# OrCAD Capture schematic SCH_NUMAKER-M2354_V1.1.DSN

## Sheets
1 Page08_LCD: size A; title: LCD interface; rev: V1.1; note: NuMaker-M2354
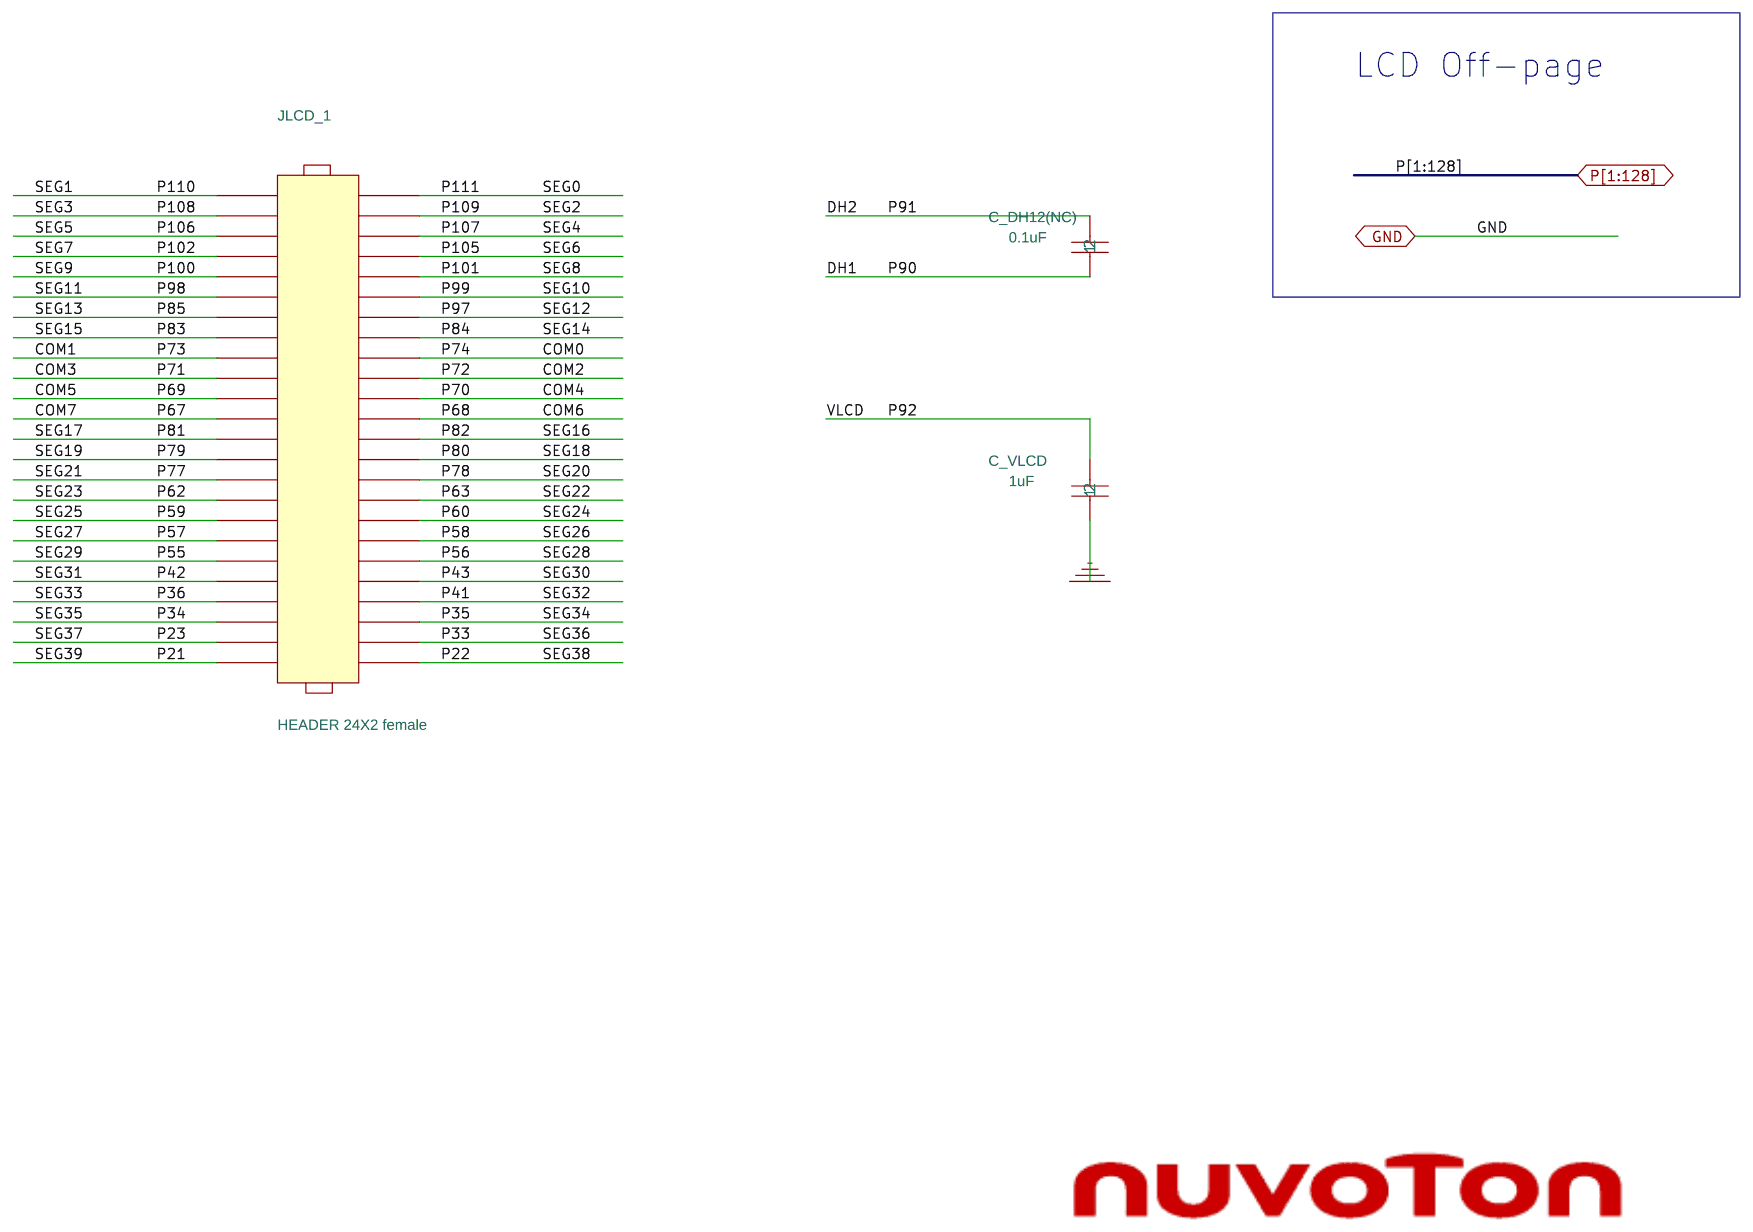
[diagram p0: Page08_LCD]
2 Page00-Nu-Link2-Me: size A3; title: Nu-Link2-Me; rev: 1.0; company: CACHEN; note: Nu-Link2-Me
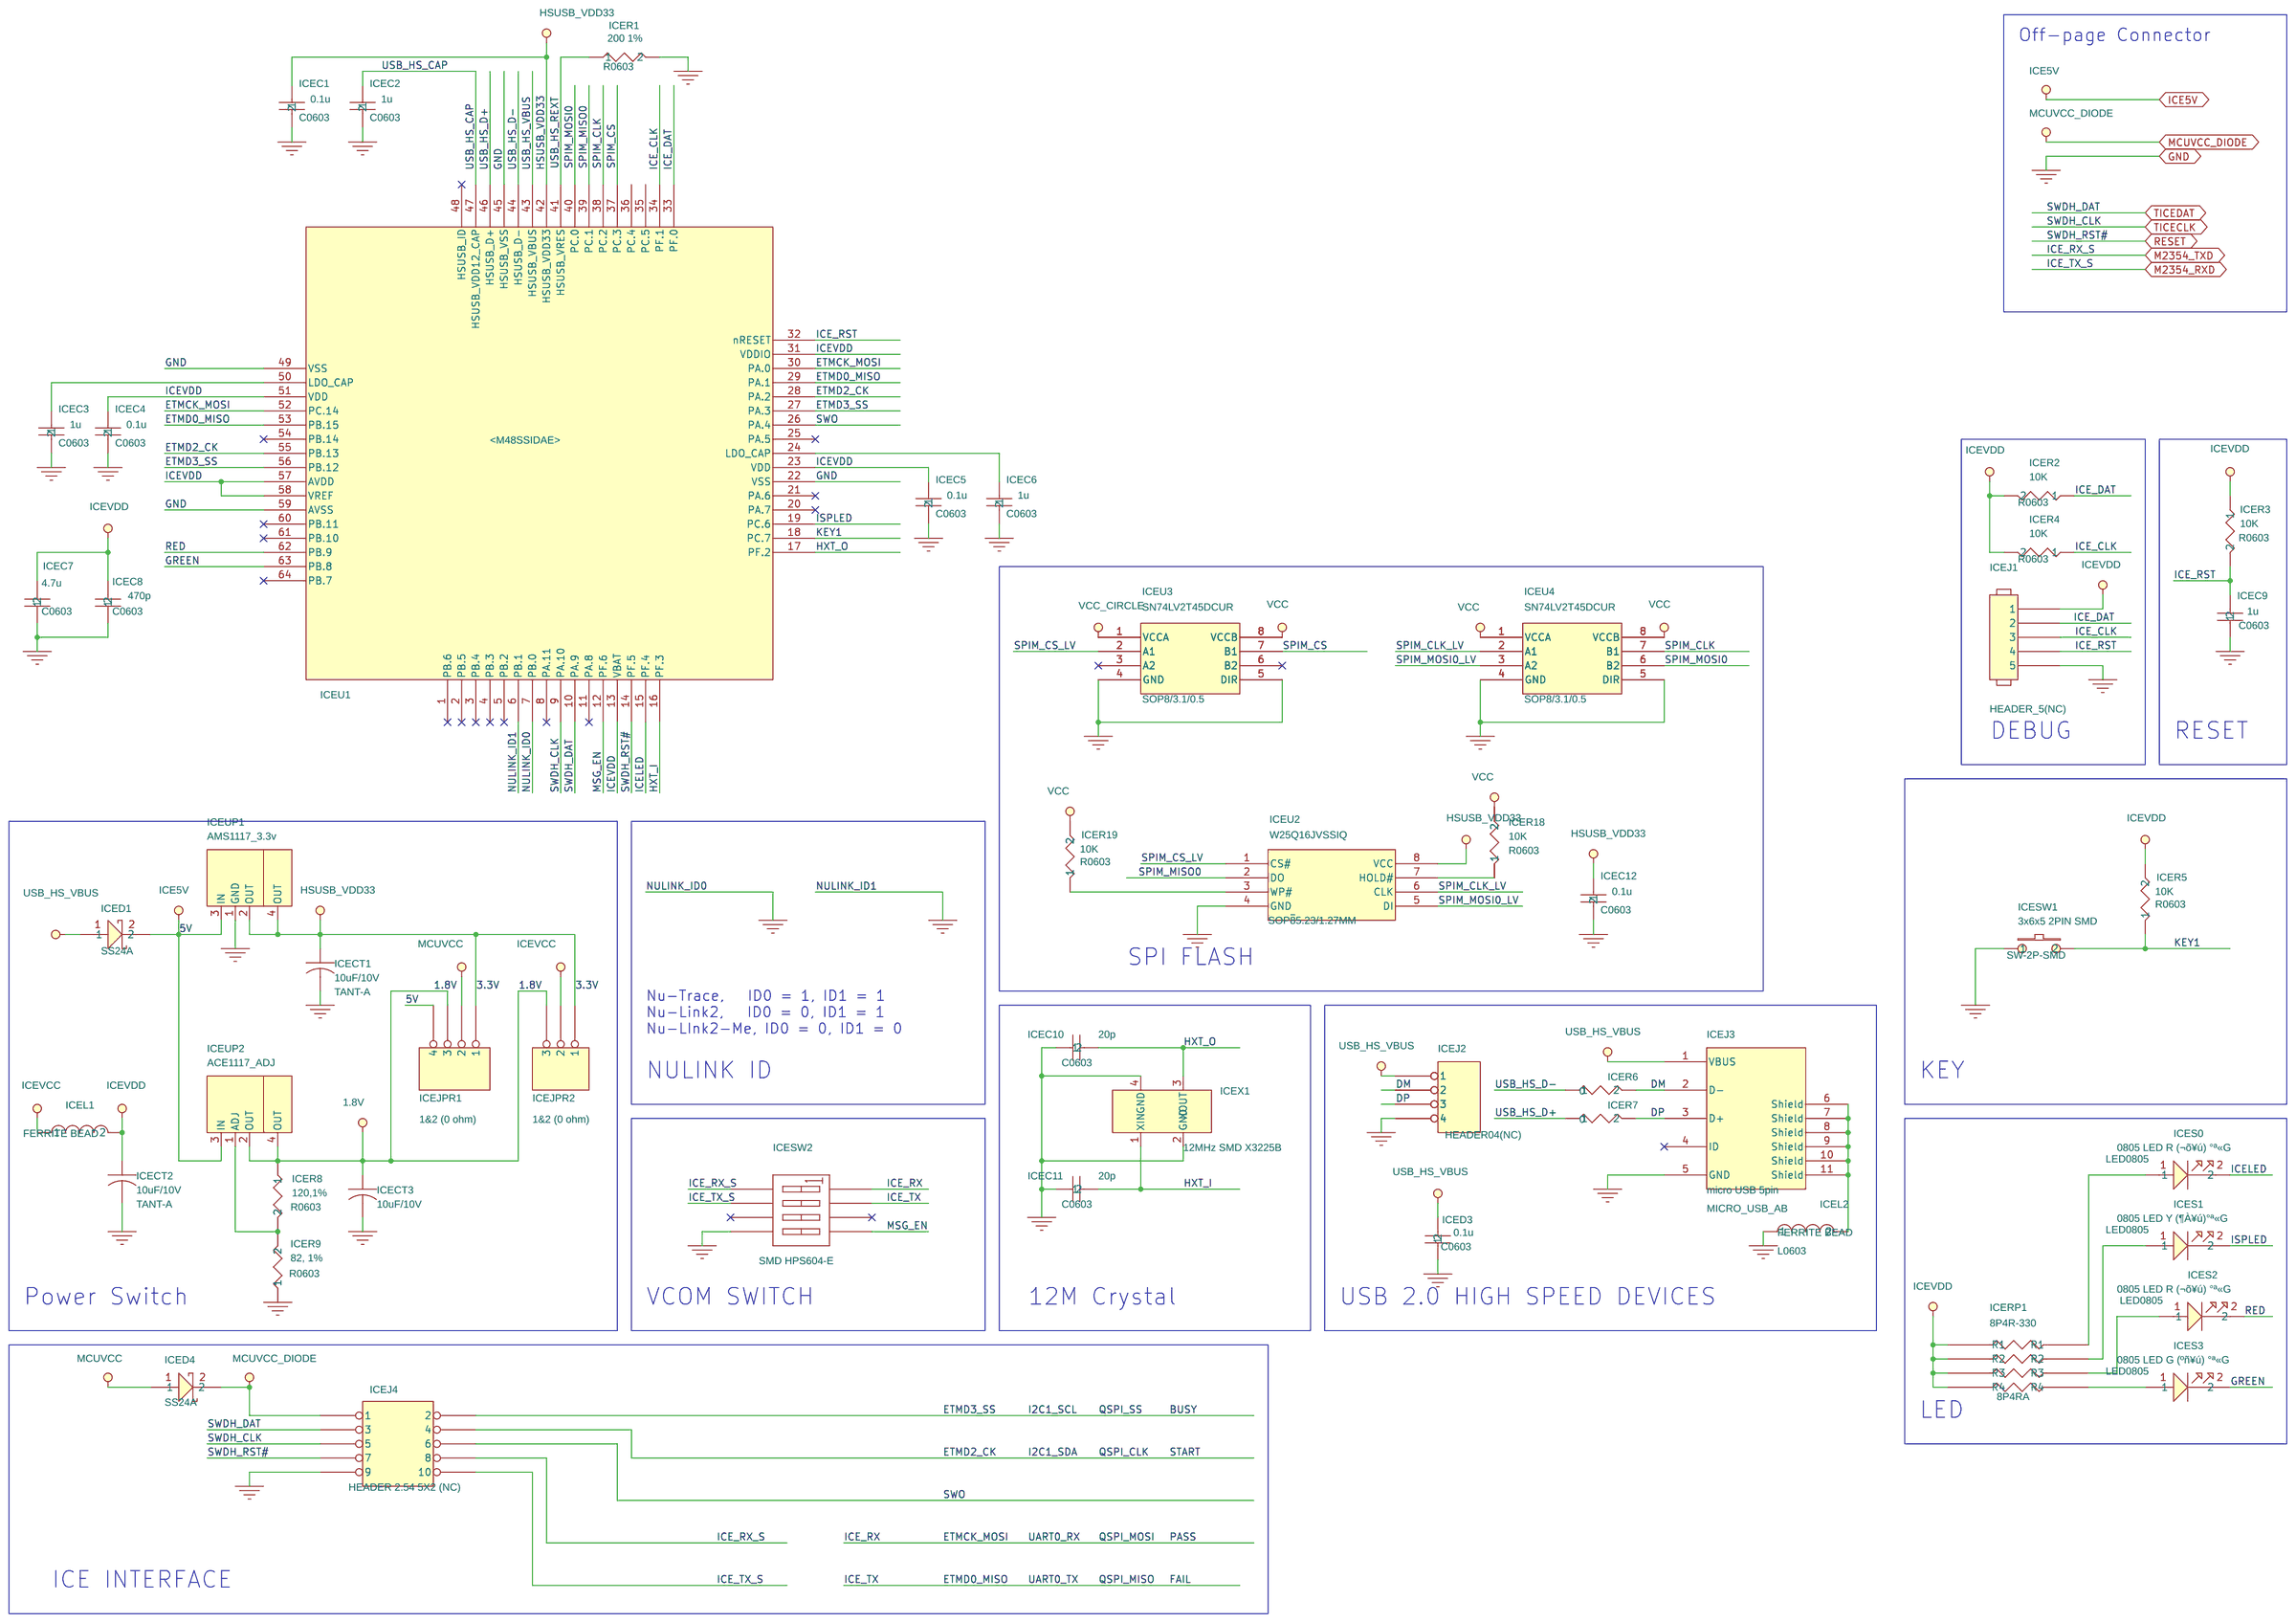
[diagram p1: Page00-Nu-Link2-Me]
3 Page07_WIFI Module: size A4; title: WIFI Module(ESP-12)
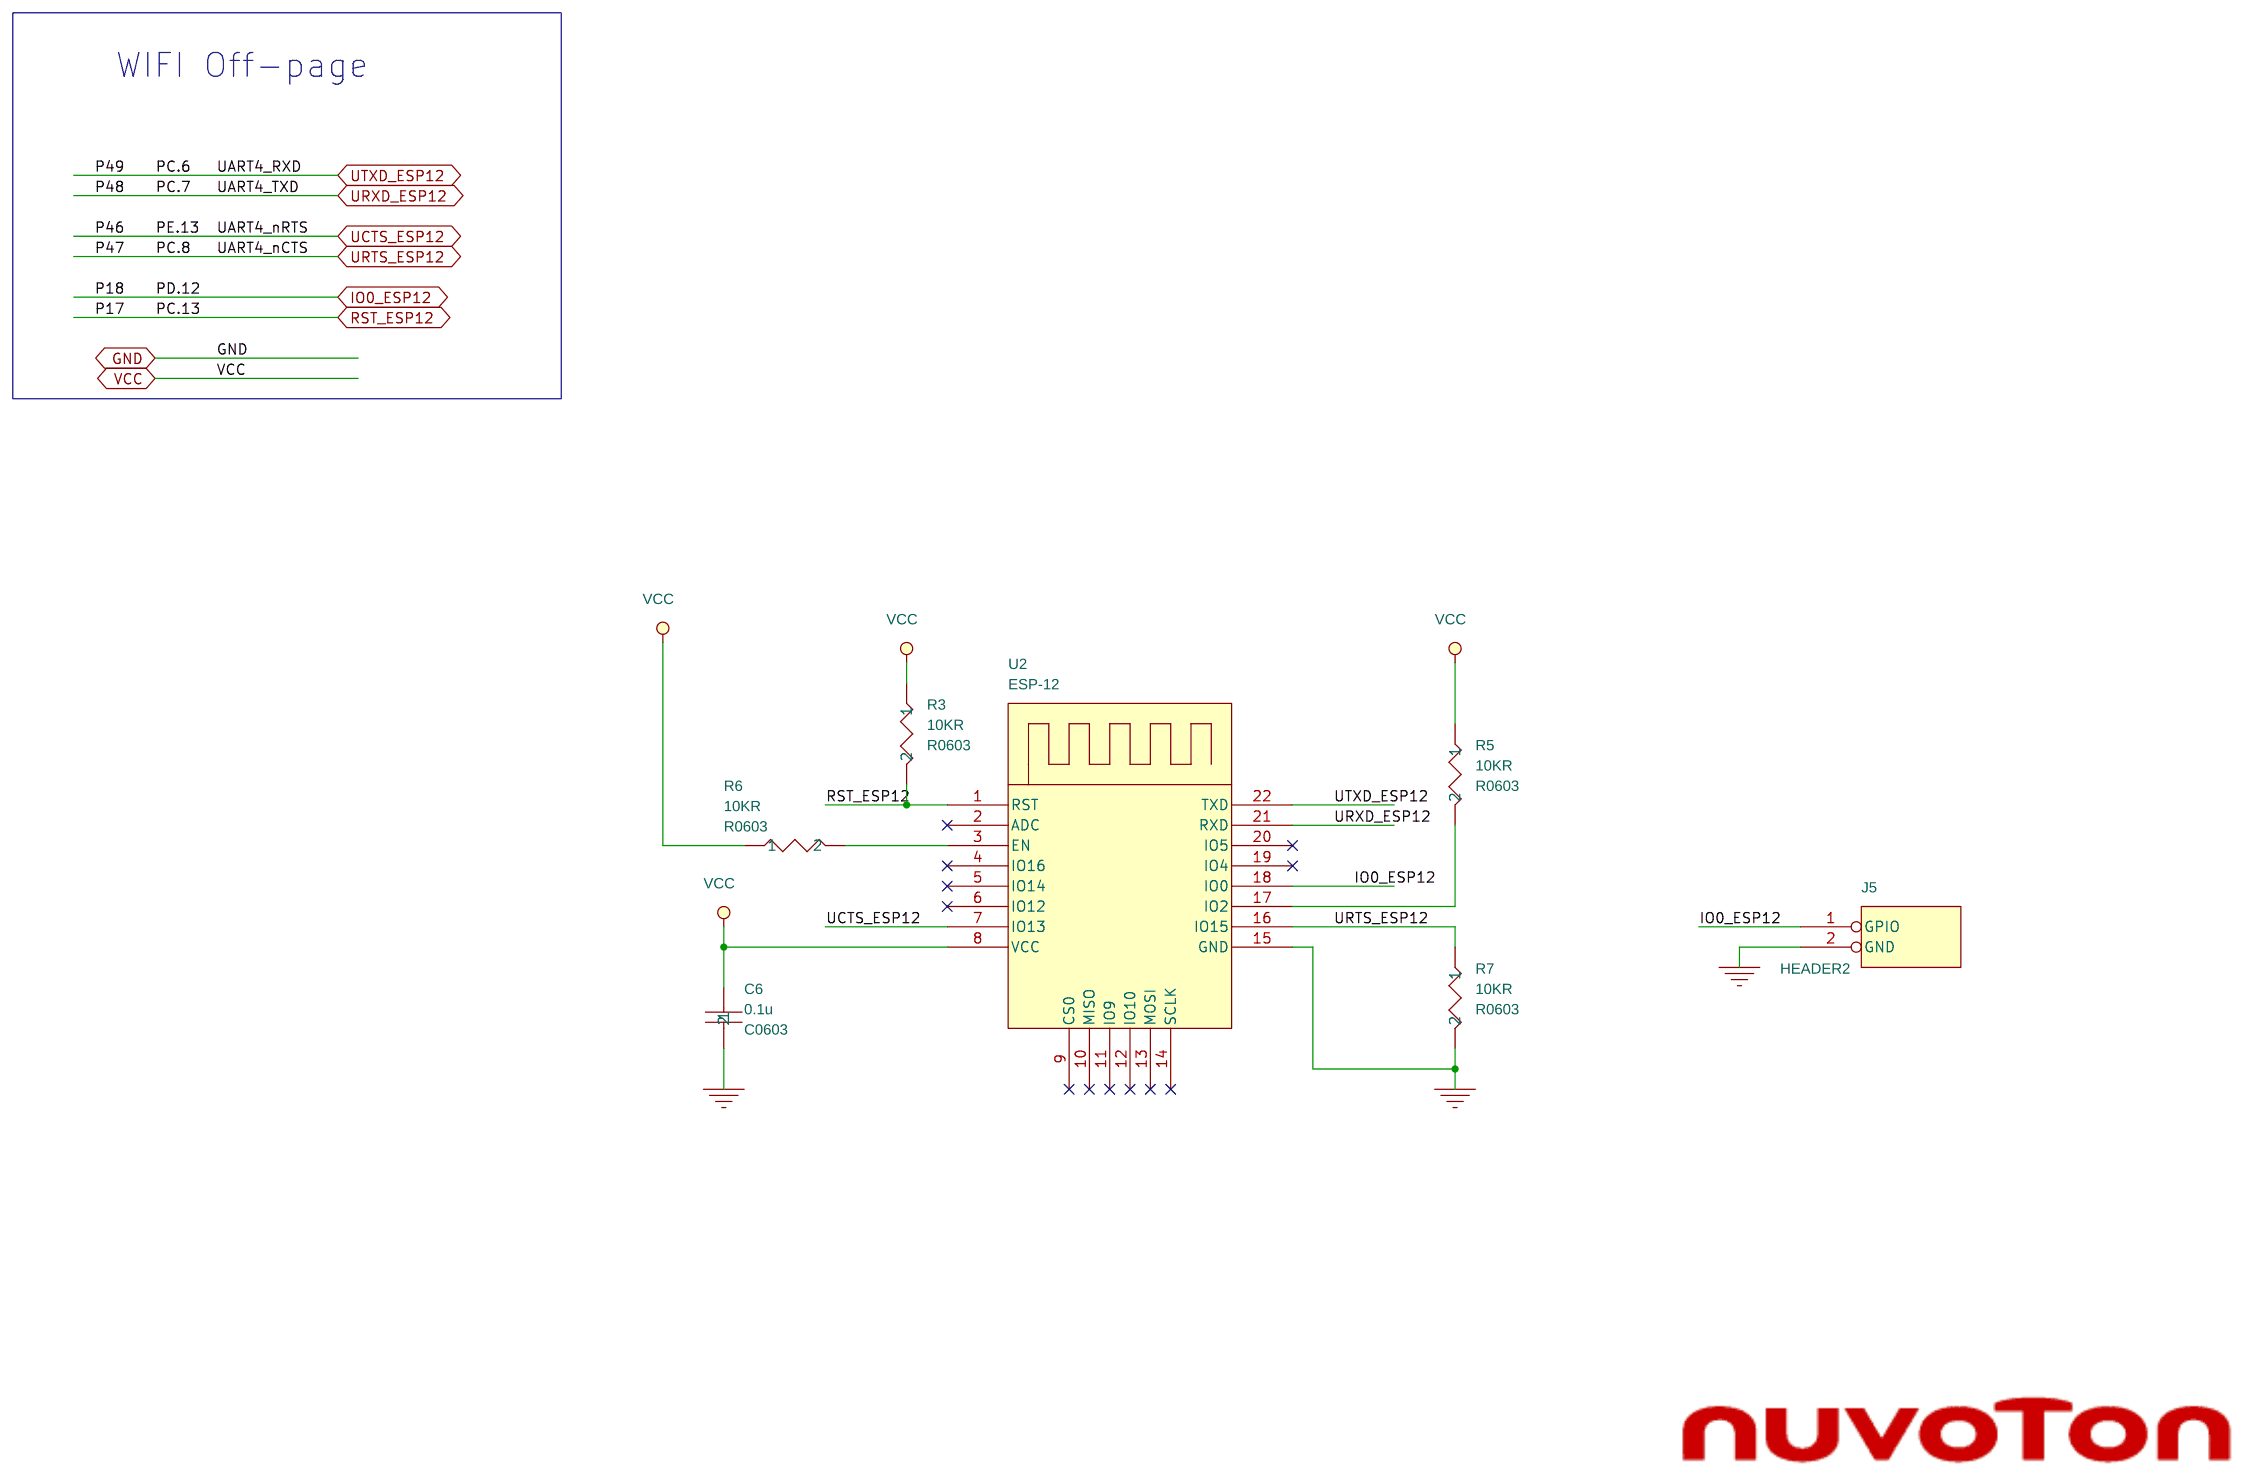
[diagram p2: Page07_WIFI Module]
4 Page01_M2354 MCU: size Custom; title: M2354KJFAE(LQFP128) MCU
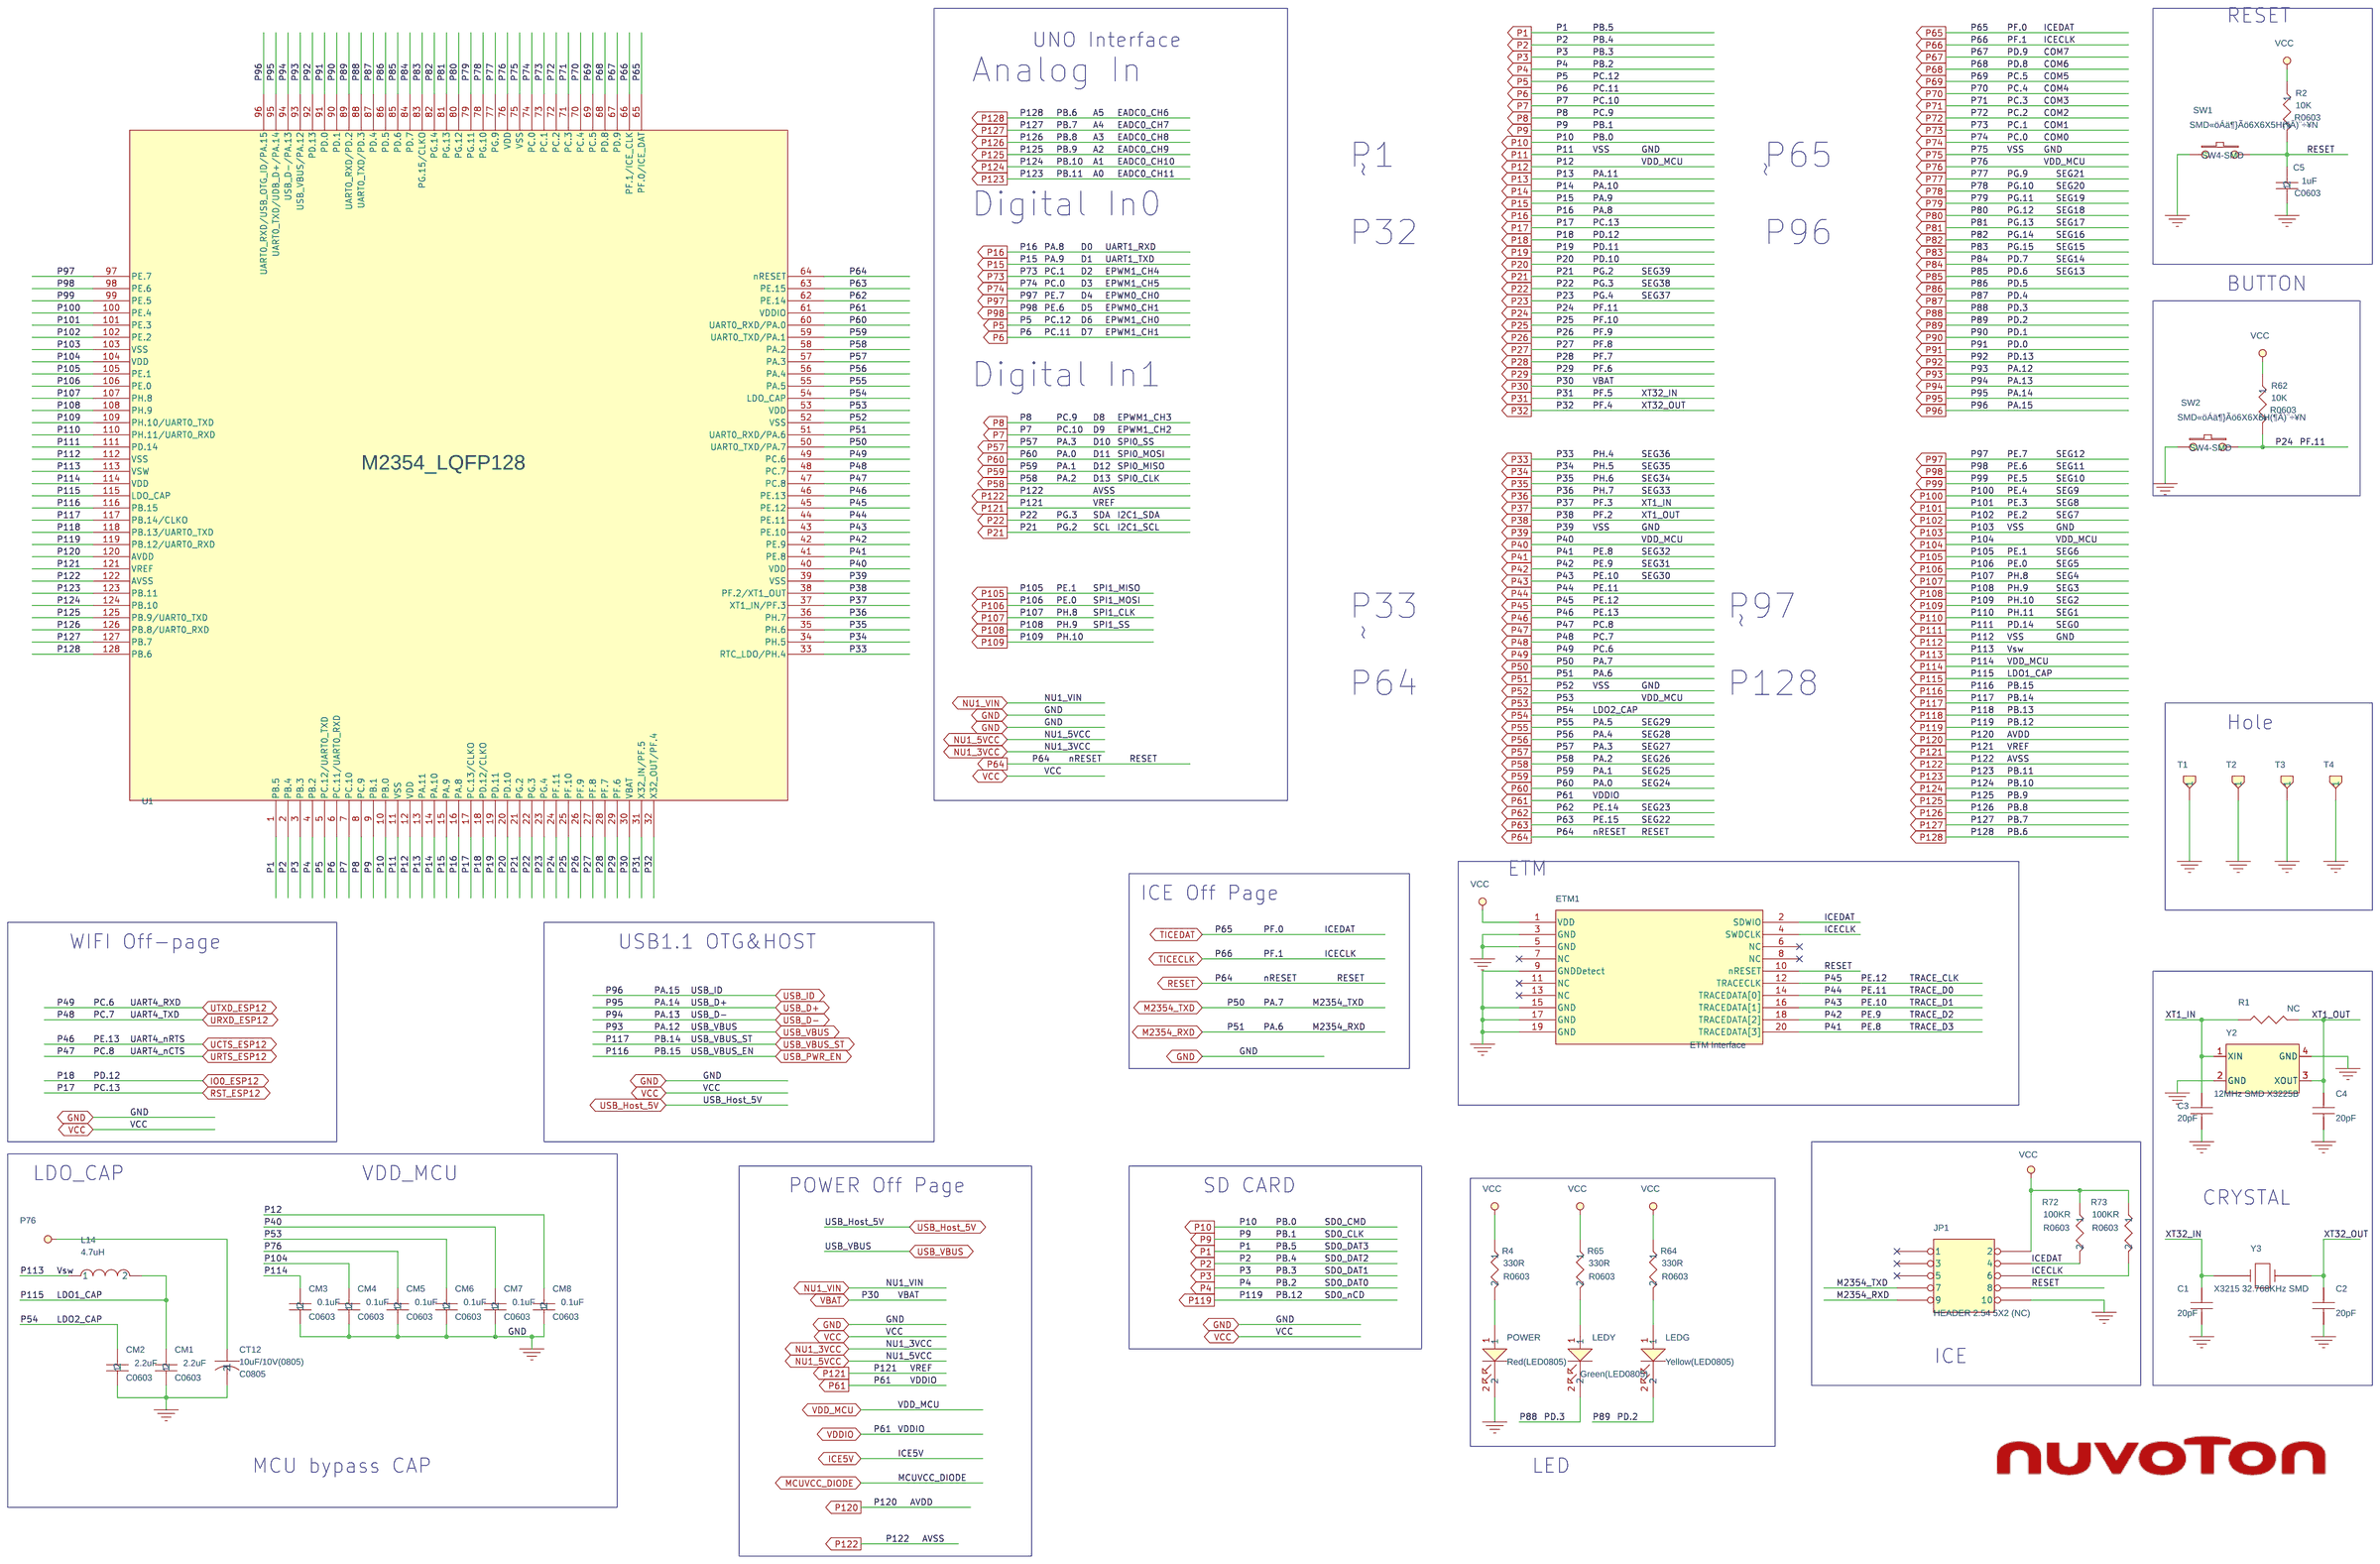
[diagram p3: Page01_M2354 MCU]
5 Page02_USB OTG Host Device: size A4; title: USB OTG
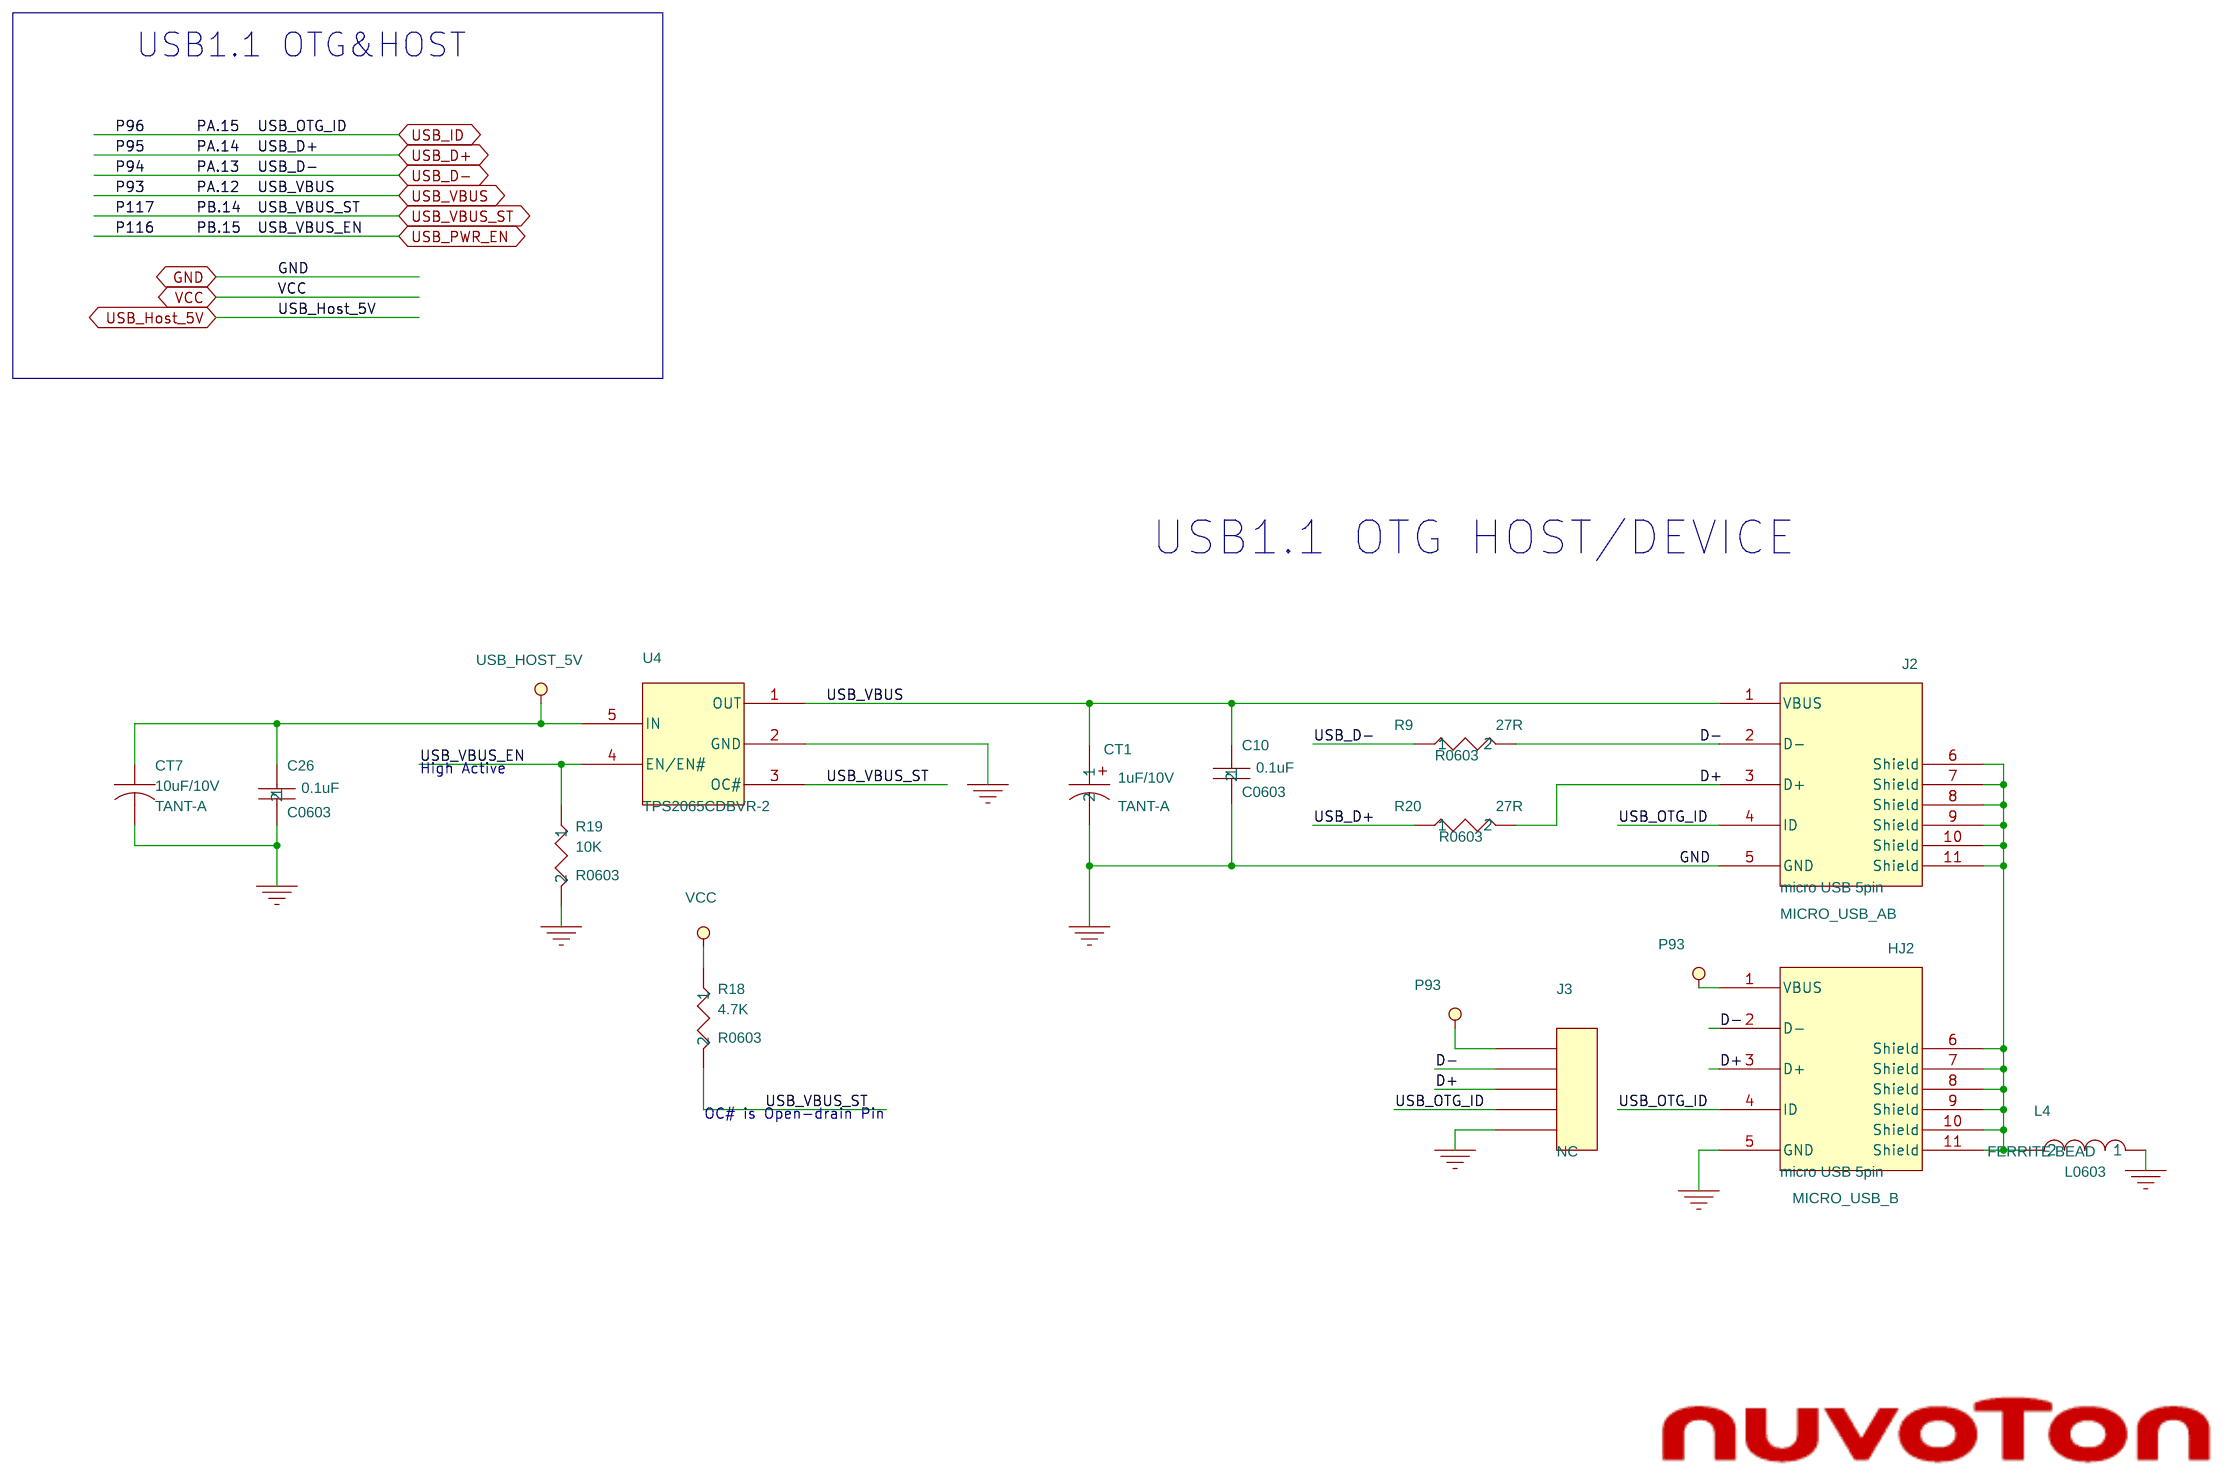
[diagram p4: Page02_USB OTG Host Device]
6 Page03_Power: size Custom; title: POWER
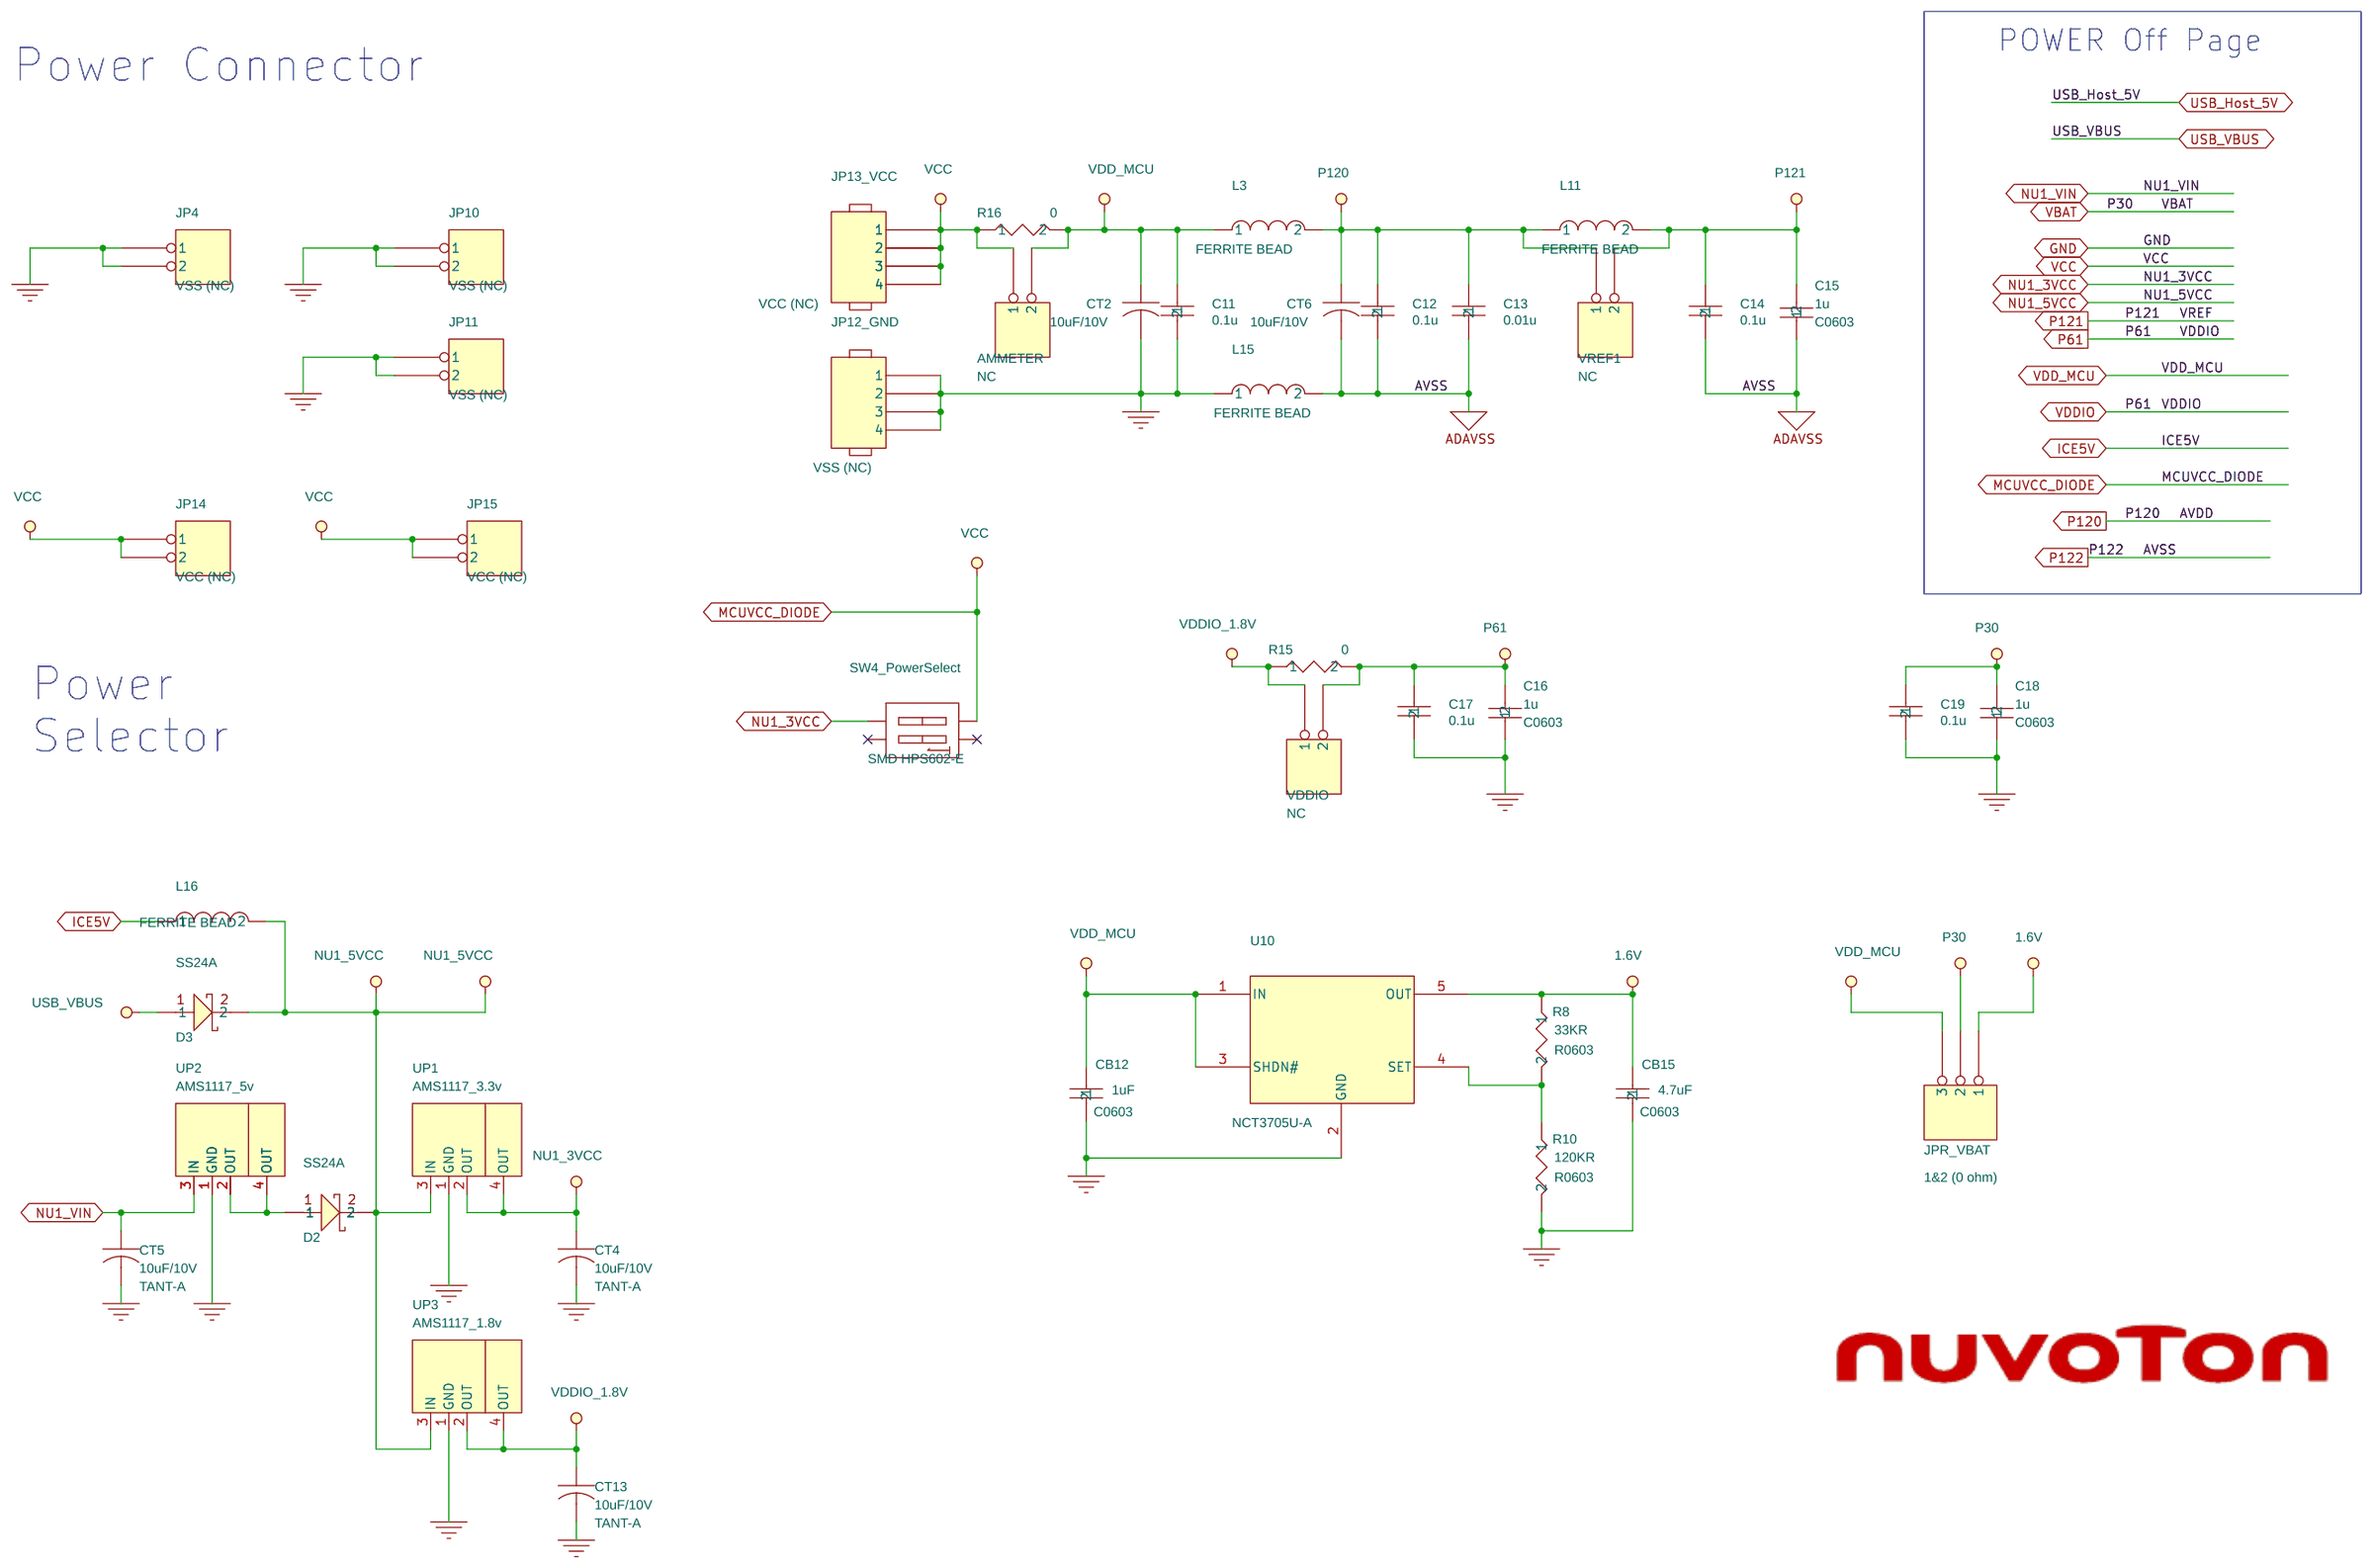
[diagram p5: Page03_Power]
7 Page04_MCU Connector: size A4; title: MCU Connector
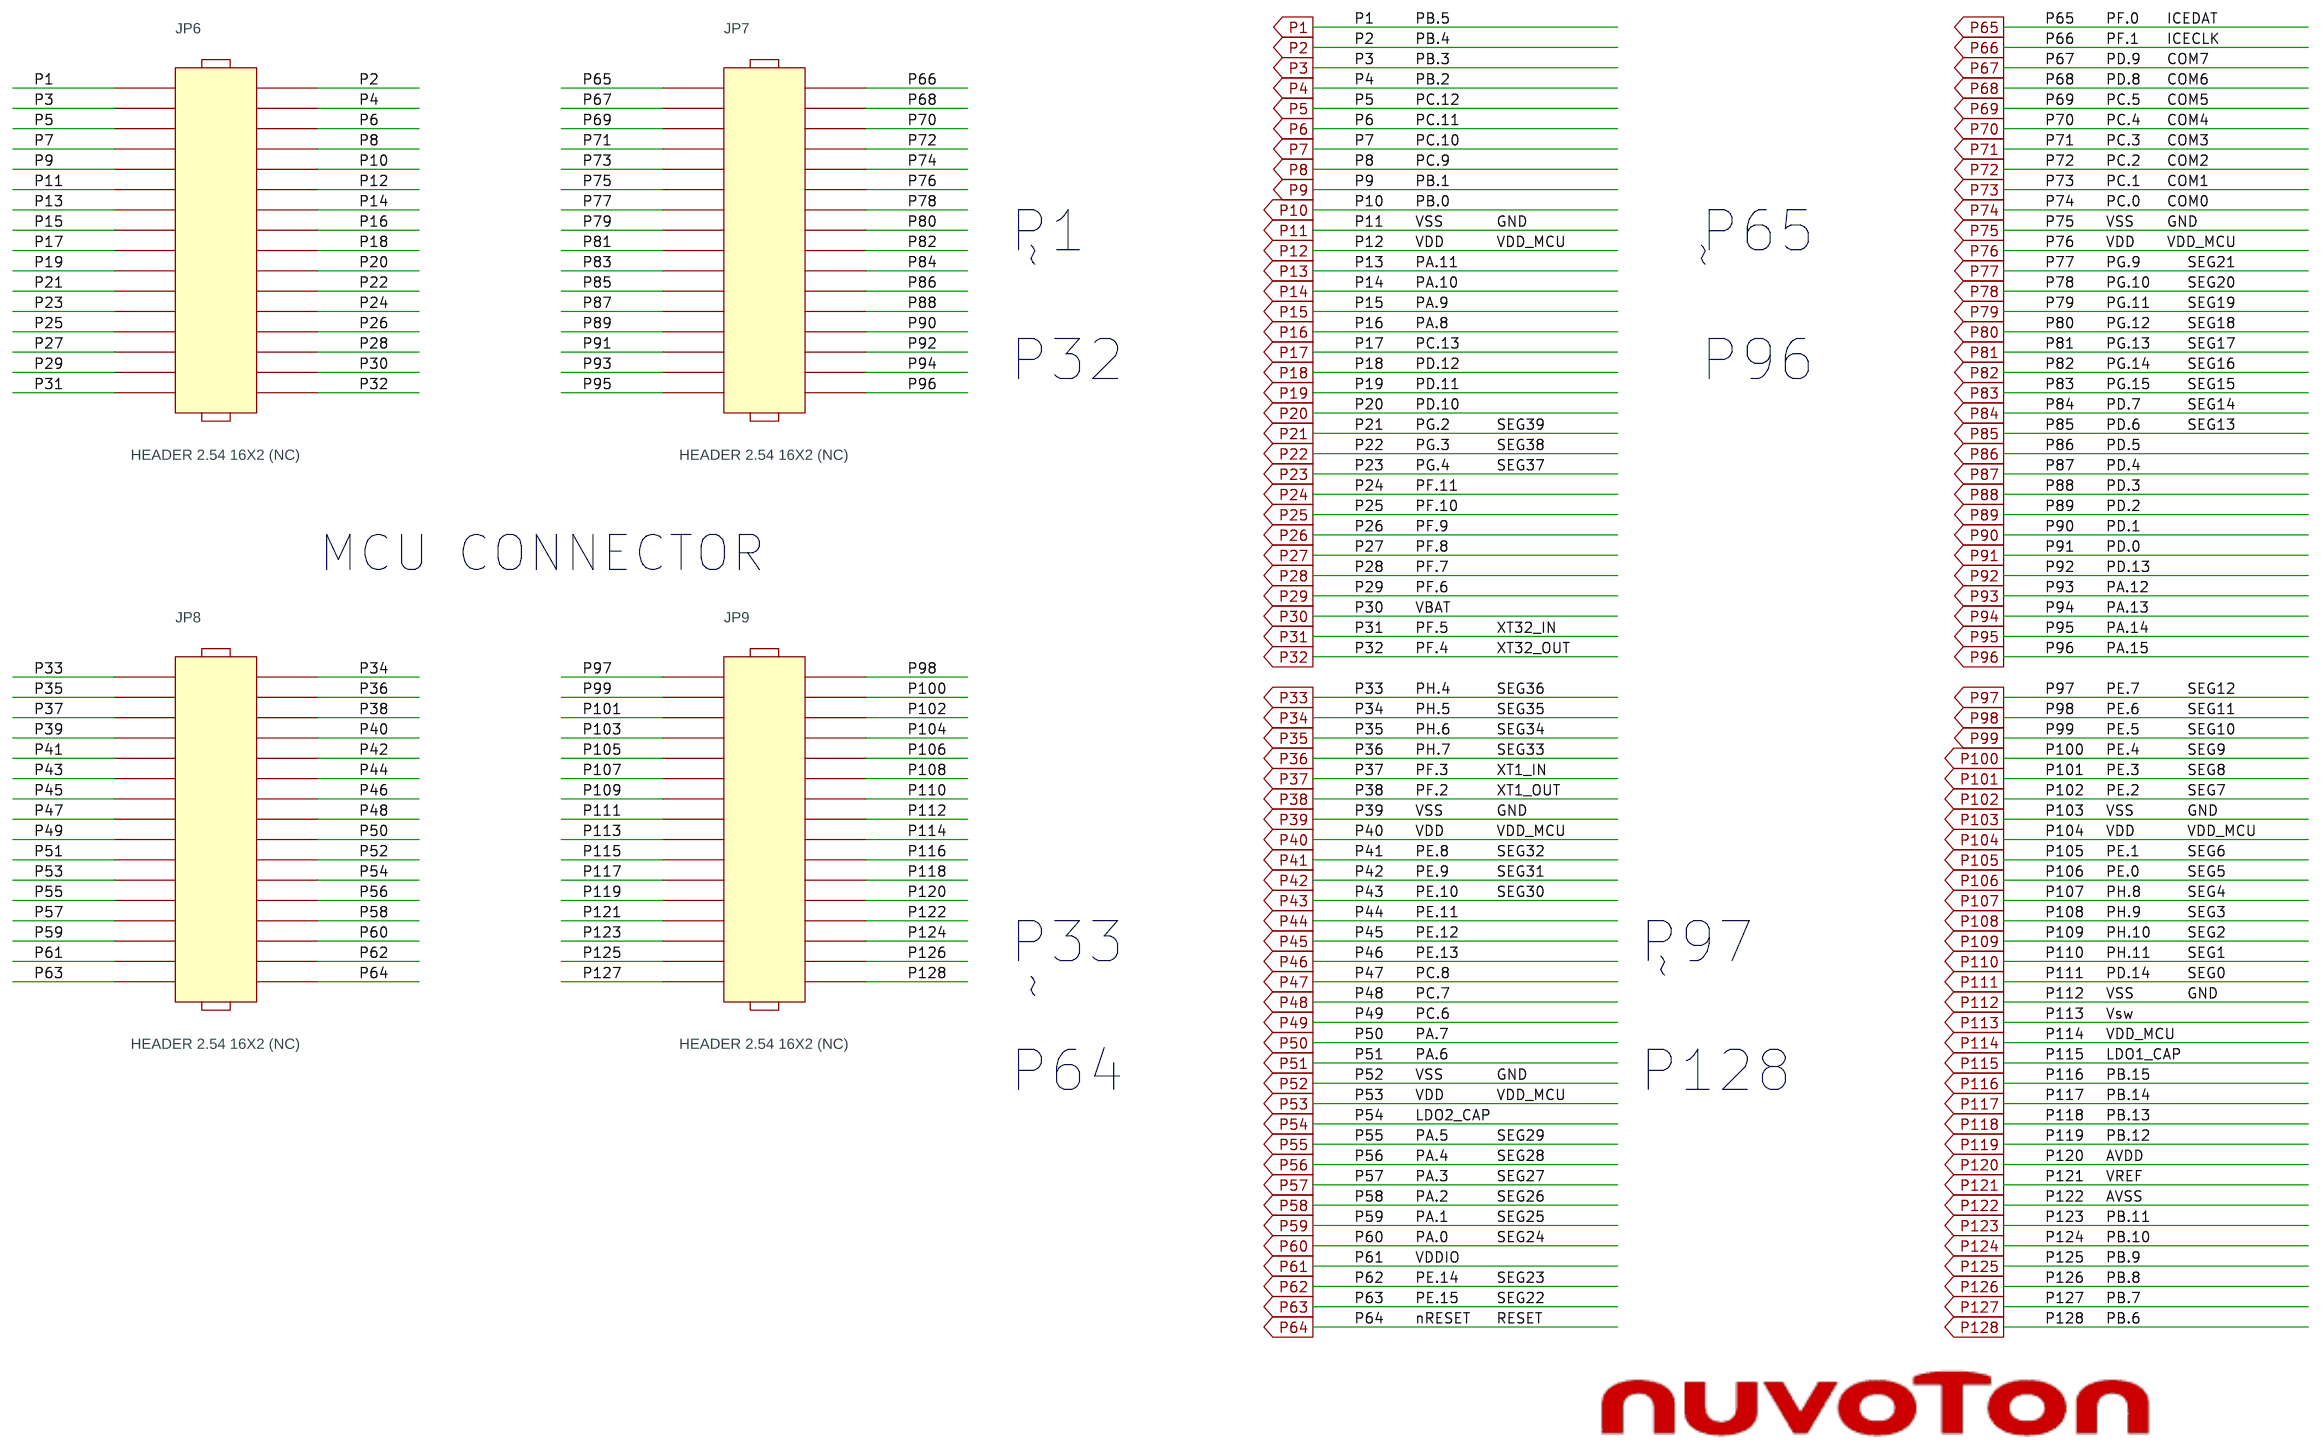
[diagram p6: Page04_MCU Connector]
8 Page05 UNO Interface Connector: size A; title: UNO Interface
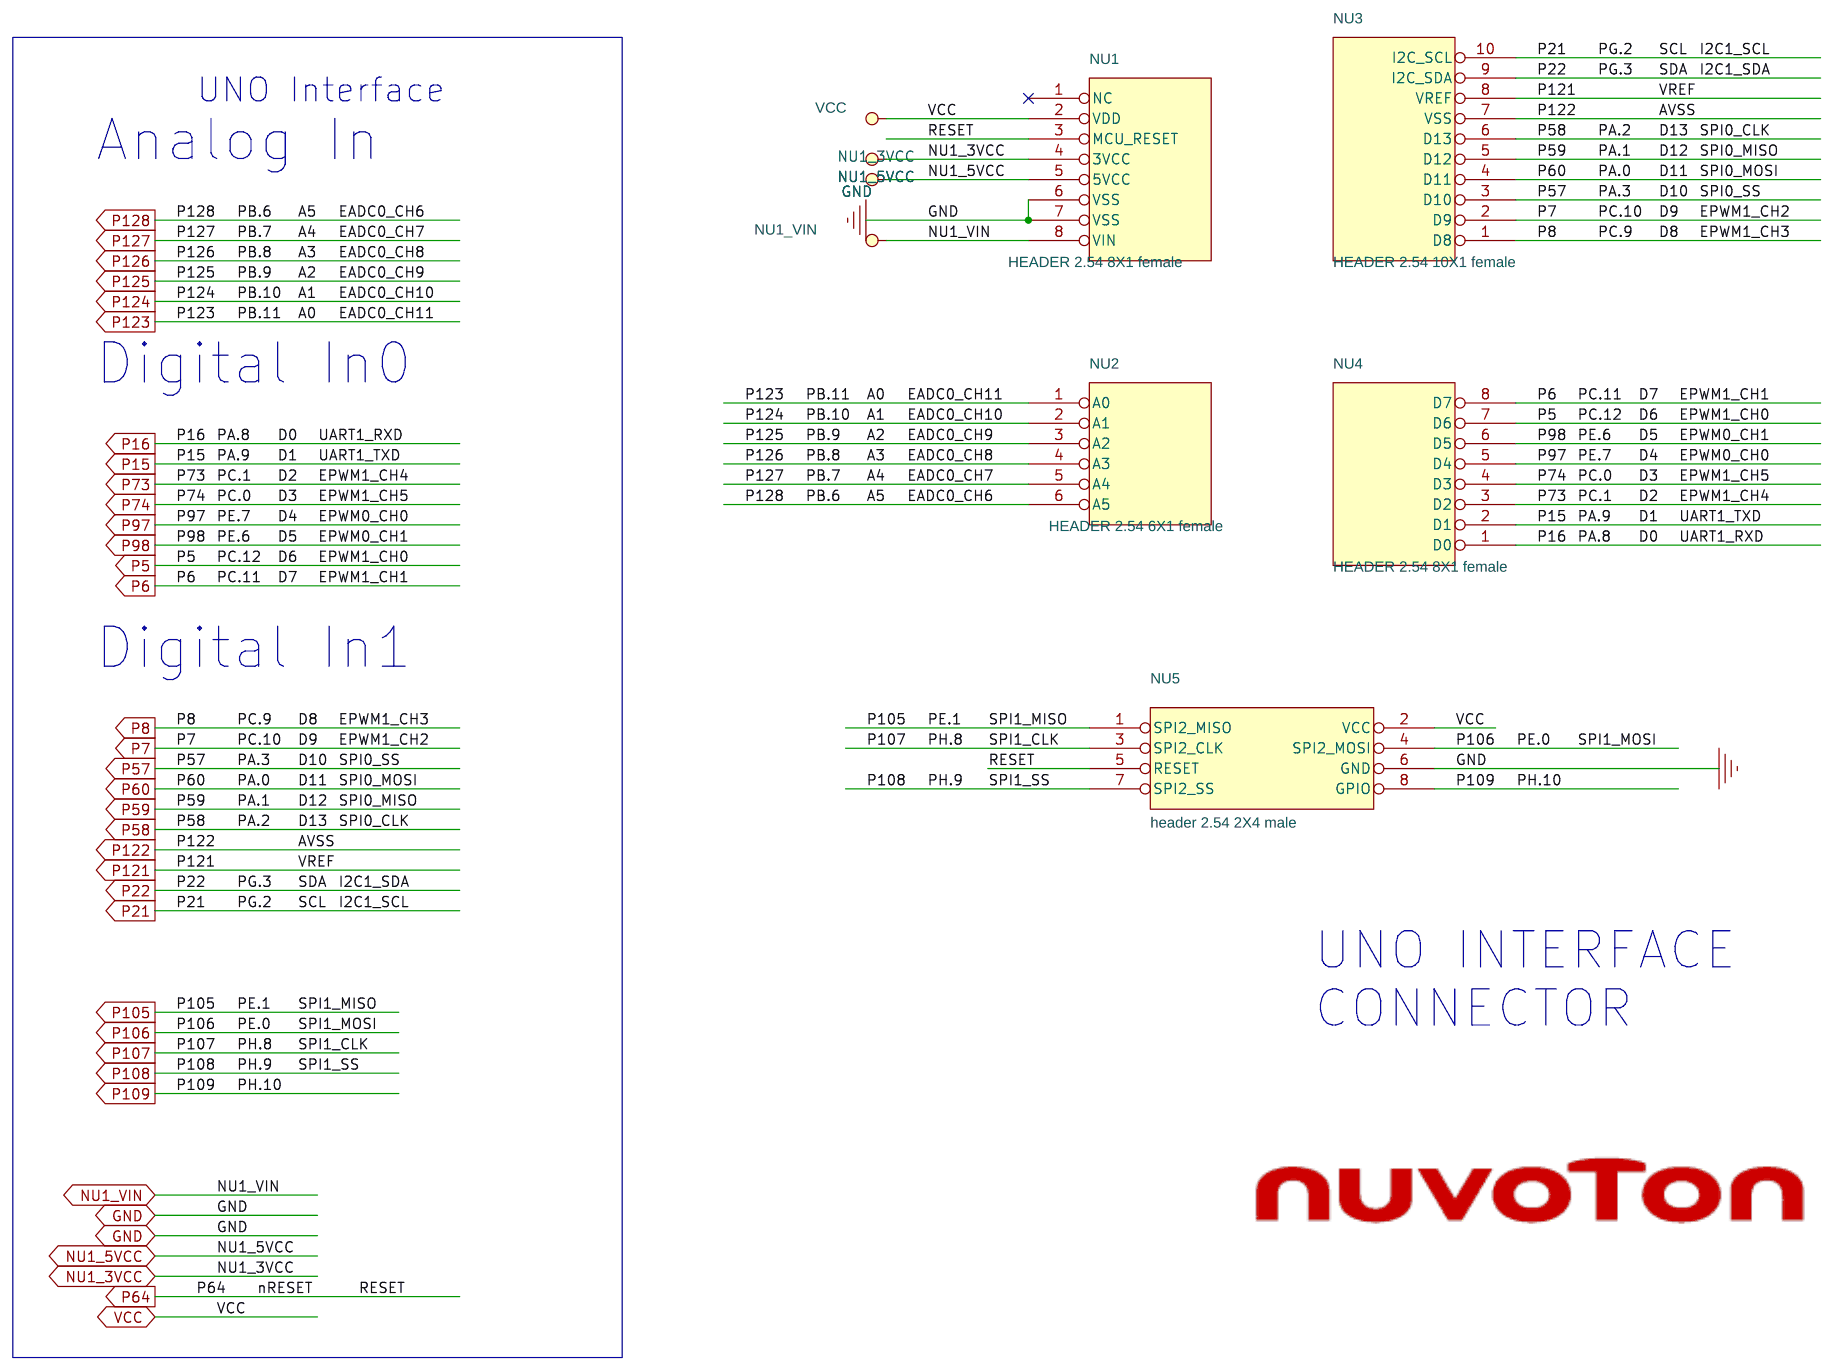
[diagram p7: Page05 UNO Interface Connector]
9 Page06_SD Card: size A4; title: SD Card
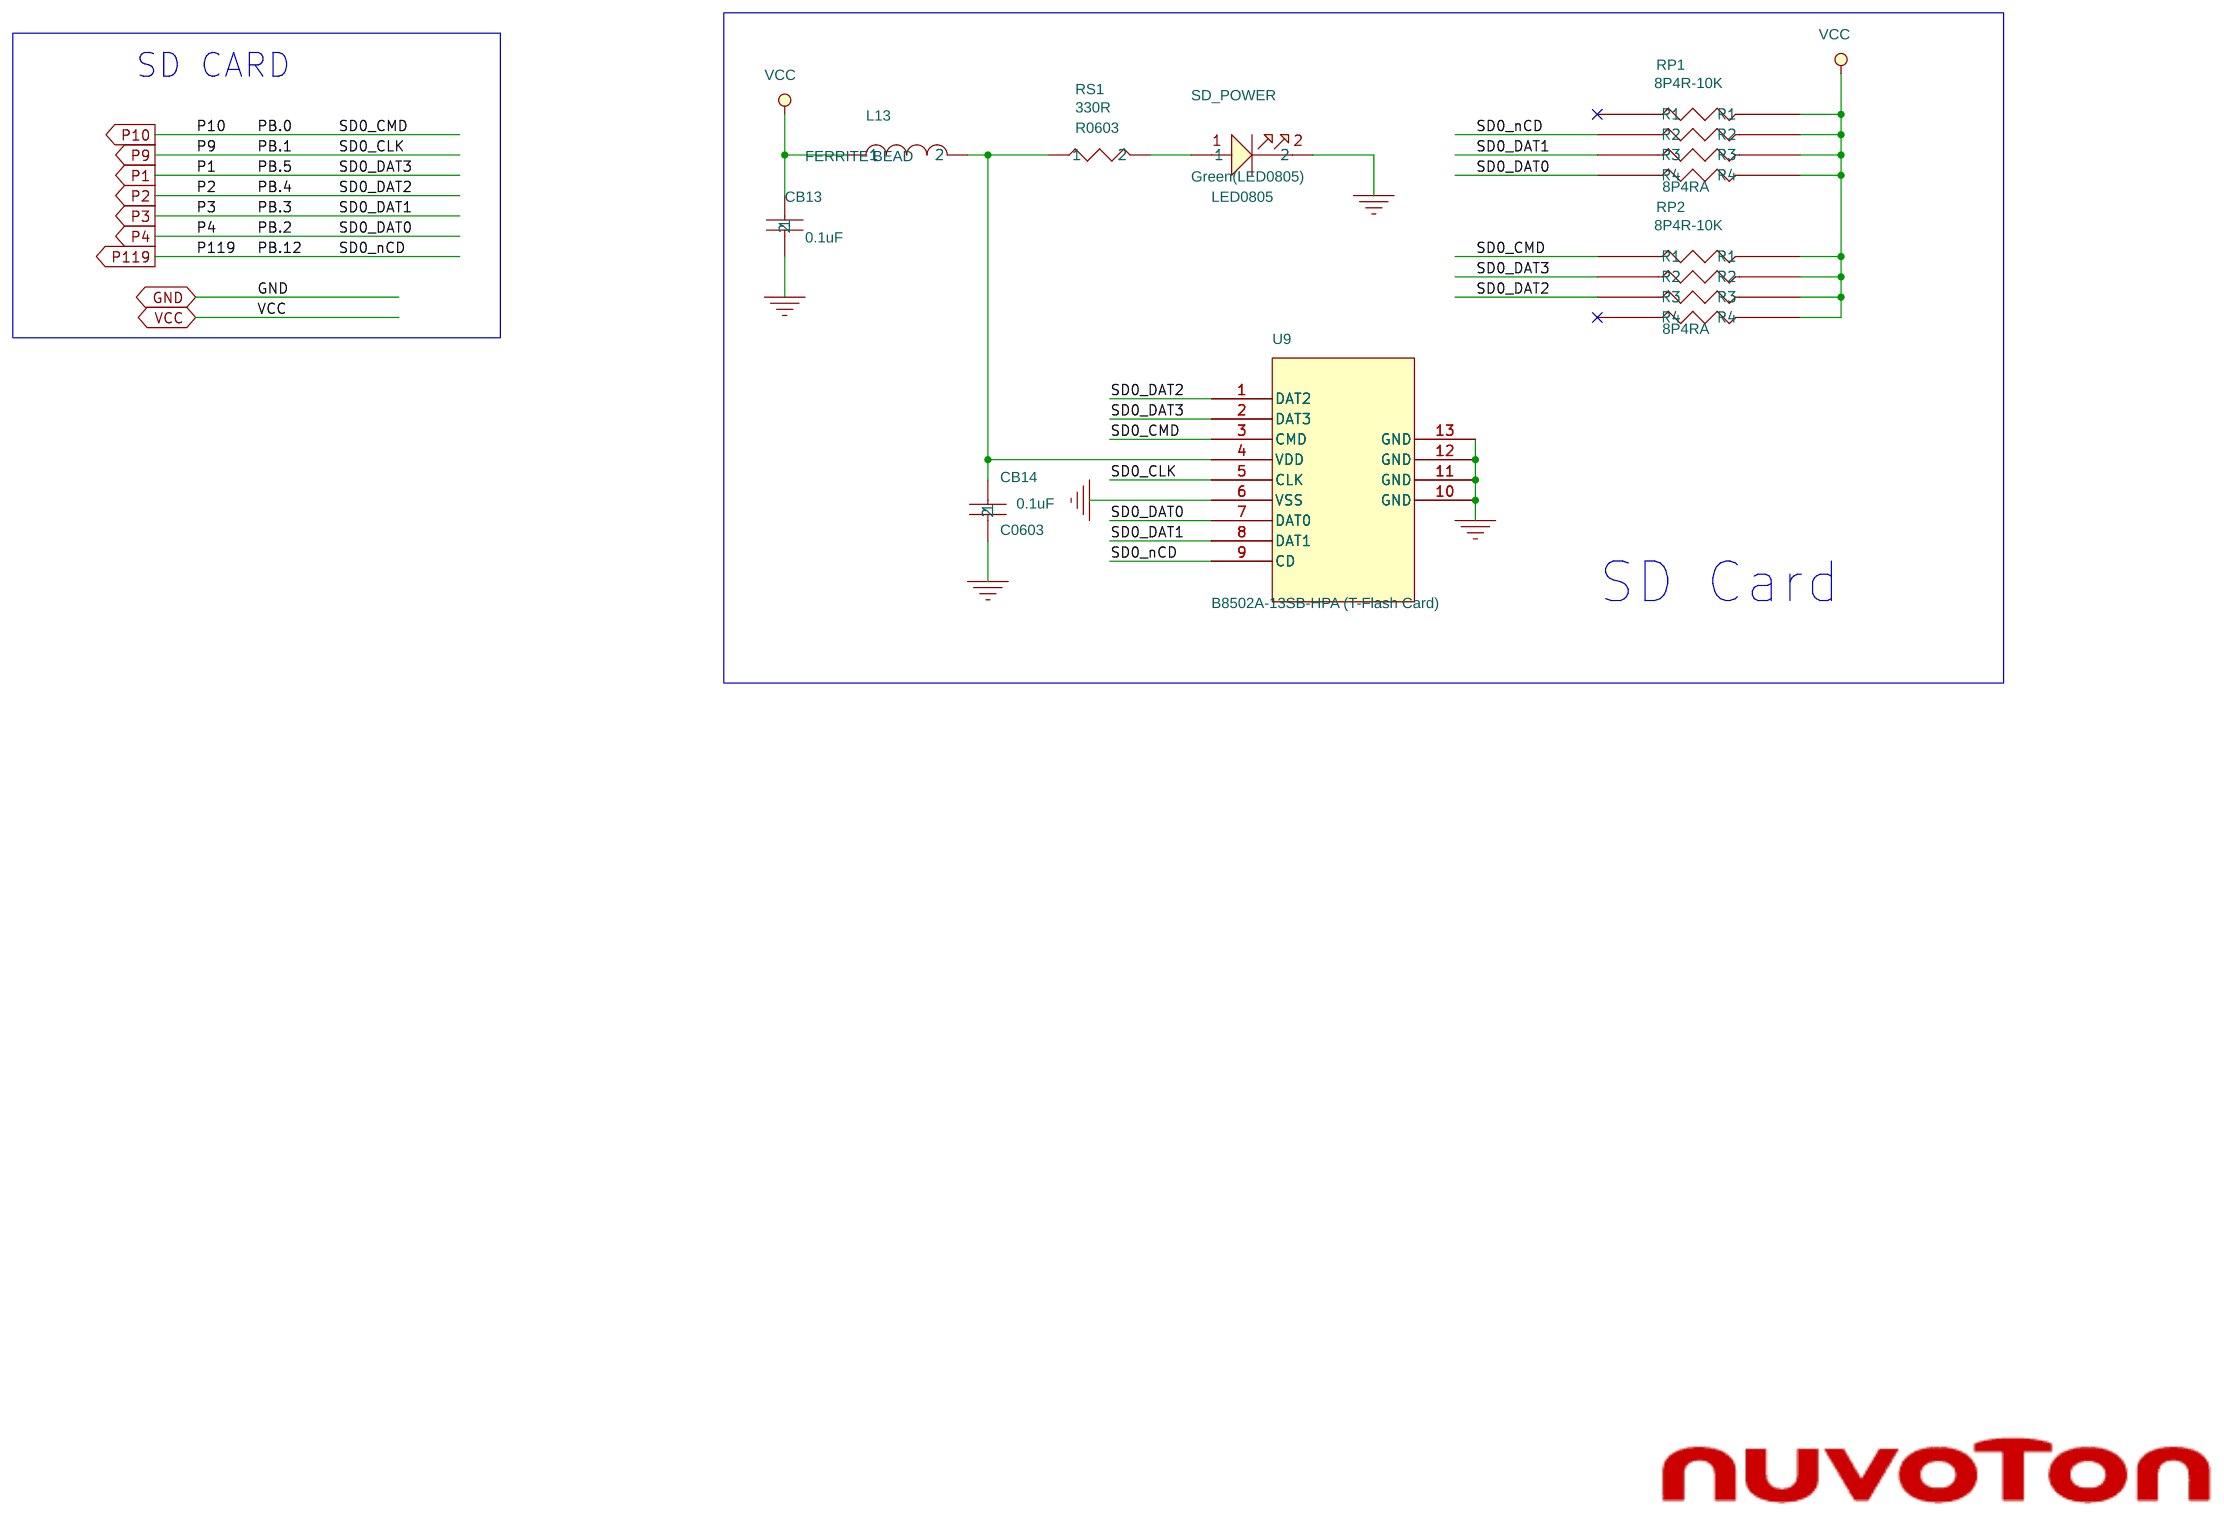
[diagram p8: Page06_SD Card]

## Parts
sheet Page00-Nu-Link2-Me
ICEC1  0.1u  [C0603]
ICEC2  1u  [C0603]
ICEC3  1u  [C0603]
ICEC4  0.1u  [C0603]
ICEC5  0.1u  [C0603]
ICEC6  1u  [C0603]
ICEC7  4.7u  [C0603]
ICEC8  470p  [C0603]
ICEC9  1u  [C0603]
ICEC10  20p  [C0603]
ICEC11  20p  [C0603]
ICEC12  0.1u  [C0603]
ICECT1  10uF/10V  [TANT-A]
ICECT2  10uF/10V  [TANT-A]
ICECT3  10uF/10V  [TANT-A]
ICED1  SS24A  [RB060L]
ICED3  0.1u  [C0603]
ICED4  SS24A  [RB060L]
ICEJ1  HEADER_5(NC)  [HEADER5X1]
ICEJ2  HEADER04(NC)  [HEADER04]
ICEJ3  micro USB 5pin  [MICRO_USB_AB]
ICEJ4  HEADER 2.54 5X2 (NC)  [HEADER5X2]
ICEJPR1  1&2 (0 ohm)  [R0603X3]
ICEJPR2  1&2 (0 ohm)  [R0603X2]
ICEL1  FERRITE BEAD  [L0603]
ICEL2  FERRITE BEAD  [L0603]
ICER1  200 1%  [R0603]
ICER2  10K  [R0603]
ICER3  10K  [R0603]
ICER4  10K  [R0603]
ICER5  10K  [R0603]
ICER6  0  [R0603]
ICER7  0  [R0603]
ICER8  120,1%  [R0603]
ICER9  82, 1%  [R0603]
ICER18  10K  [R0603]
ICER19  10K  [R0603]
ICERP1  8P4R-330  [8P4RA]
ICES0  0805 LED R (¬õ¥ú) °ª«G  [LED0805]
ICES1  0805 LED Y (¶À¥ú)°ª«G  [LED0805]
ICES2  0805 LED R (¬õ¥ú) °ª«G  [LED0805]
ICES3  0805 LED G (ºñ¥ú) °ª«G  [LED0805]
ICESW1  3x6x5 2PIN SMD  [SW-2P-SMD]
ICESW2  SMD HPS604-E  [SW1X4]
ICEU1  M48SSIDAE  [LQFP64_7x7_M48SSIDAE]
ICEU2  W25Q16JVSSIQ  [SOP8\5.23/1.27MM]
ICEU3  SN74LV2T45DCUR  [SOP8/3.1/0.5]
ICEU4  SN74LV2T45DCUR  [SOP8/3.1/0.5]
ICEUP1  AMS1117_3.3v  [SOT-223-1]
ICEUP2  ACE1117_ADJ  [SOT-223-1]
ICEX1  12MHz SMD X3225B  [CRYSTAL_SMD]
sheet Page01_M2354 MCU
C1  20pF  [C0603]
C2  20pF  [C0603]
C3  20pF  [C0603]
C4  20pF  [C0603]
C5  1uF  [C0603]
CM1  2.2uF  [C0603]
CM2  2.2uF  [C0603]
CM3  0.1uF  [C0603]
CM4  0.1uF  [C0603]
CM5  0.1uF  [C0603]
CM6  0.1uF  [C0603]
CM7  0.1uF  [C0603]
CM8  0.1uF  [C0603]
CT12  10uF/10V(0805)  [C0805]
ETM1  ETM Interface  [FTHS_1.27_ES_10X2]
JP1  HEADER 2.54 5X2 (NC)  [HEADER5X2]
L14  4.7uH  [L-VLF403215MT]
LEDG  Yellow(LED0805)  [LED0805]
LEDY  Green(LED0805)  [LED0805]
POWER  Red(LED0805)  [LED0805]
R1  NC  [R0603]
R2  10K  [R0603]
R4  330R  [R0603]
R62  10K  [R0603]
R64  330R  [R0603]
R65  330R  [R0603]
R72  100KR  [R0603]
R73  100KR  [R0603]
SW1  SMD«öÁä¶}Ãö6X6X5H(¶Â)¨÷¥N  [SW4-SMD]
SW2  SMD«öÁä¶}Ãö6X6X5H(¶Â)¨÷¥N  [SW4-SMD]
T1  T POINT(NC)  [H-3.4X6]
T2  T POINT(NC)  [H-3.4X6]
T3  T POINT(NC)  [H-3.4X6]
T4  T POINT(NC)  [H-3.4X6]
U1  TC8226LQFP144  [LQFP128]
Y2  12MHz SMD X3225B  [XRGBBCNANF-27M]
Y3  X3215 32.768KHz SMD  [9HT9]
sheet Page02_USB OTG Host Device
C10  0.1uF  [C0603]
C26  0.1uF  [C0603]
CT1  1uF/10V  [TANT-A]
CT7  10uF/10V  [TANT-A]
HJ2  micro USB 5pin  [MICRO_USB_B]
J2  micro USB 5pin  [MICRO_USB_AB]
J3  NC  [HEADER5X1]
L4  FERRITE BEAD  [L0603]
R9  27R  [R0603]
R18  4.7K  [R0603]
R19  10K  [R0603]
R20  27R  [R0603]
U4  TPS2065CDBVR-2  [SOT23-5]
sheet Page03_Power
AMMETER  NC  [HEADER2X1]
C11  0.1u  [C0603]
C12  0.1u  [C0603]
C13  0.01u  [C0603]
C14  0.1u  [C0603]
C15  1u  [C0603]
C16  1u  [C0603]
C17  0.1u  [C0603]
C18  1u  [C0603]
C19  0.1u  [C0603]
CB12  1uF  [C0603]
CB15  4.7uF  [C0603]
CT2  10uF/10V  [TANT-A]
CT4  10uF/10V  [TANT-A]
CT5  10uF/10V  [TANT-A]
CT6  10uF/10V  [TANT-A]
CT13  10uF/10V  [TANT-A]
D2  SS24A  [RB060L]
D3  SS24A  [RB060L]
JP4  VSS (NC)  [HEADER2]
JP10  VSS (NC)  [HEADER2]
JP11  VSS (NC)  [HEADER2]
JP12_GND  VSS (NC)  [header1x4]
JP13_VCC  VCC (NC)  [header1x4]
JP14  VCC (NC)  [HEADER2]
JP15  VCC (NC)  [HEADER2]
JPR_VBAT  1&2 (0 ohm)  [R0603X2]
L3  FERRITE BEAD  [L0603]
L11  FERRITE BEAD  [L0603]
L15  FERRITE BEAD  [L0603]
L16  FERRITE BEAD  [L0603]
R8  33KR  [R0603]
R10  120KR  [R0603]
R15  0  [R0603]
R16  0  [R0603]
SW4_PowerSelect  SMD HPS602-E  [SW1X2]
U10  NCT3705U-A  [SOT23-5]
UP1  AMS1117_3.3v  [SOT-223-1]
UP2  AMS1117_5v  [SOT-223-1]
UP3  AMS1117_1.8v  [SOT-223-1]
VDDIO  NC  [HEADER2X1]
VREF1  NC  [HEADER2X1]
sheet Page04_MCU Connector
JP6  HEADER 2.54 16X2 (NC)  [HEADER16X2]
JP7  HEADER 2.54 16X2 (NC)  [HEADER16X2]
JP8  HEADER 2.54 16X2 (NC)  [HEADER16X2]
JP9  HEADER 2.54 16X2 (NC)  [HEADER16X2]
sheet Page05 UNO Interface Connector
NU1  HEADER 2.54 8X1 female  [SIP-8P]
NU2  HEADER 2.54 6X1 female  [SIP-6P]
NU3  HEADER 2.54 10X1 female  [SIP-10P]
NU4  HEADER 2.54 8X1 female  [SIP-8P]
NU5  header 2.54 2X4 male  [HEADER4X2]
sheet Page06_SD Card
CB13  0.1uF  [C0603]
CB14  0.1uF  [C0603]
L13  FERRITE BEAD  [L0603]
RP1  8P4R-10K  [8P4RA]
RP2  8P4R-10K  [8P4RA]
RS1  330R  [R0603]
SD_POWER  Green(LED0805)  [LED0805]
U9  B8502A-13SB-HPA (T-Flash Card)  [B8502A-13SB-HPA]
sheet Page07_WIFI Module
C6  0.1u  [C0603]
J5  HEADER2  [HEADER2]
R3  10KR  [R0603]
R5  10KR  [R0603]
R6  10KR  [R0603]
R7  10KR  [R0603]
U2  ESP-12  [ESP-12_MODULE]
sheet Page08_LCD
C_DH12(NC)  0.1uF  [C0603]
C_VLCD  1uF  [C0603]
JLCD_1  HEADER 24X2 female  [HEADER24X2_2mm]

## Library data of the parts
ICEC1 = CAP-C_11: Package: 0603; element_no: C0004
ICEC2 = CAP-C_2: Package: 0603; element_no: C0006
ICEC3 = CAP-C_12: Package: 0603; element_no: C0006
ICEC4 = CAP-C_1: Package: 0603; element_no: C0004
ICEC5 = CAP-C_3: Package: 0603; element_no: C0004
C16 ICEC6 = CAP-C_4: Package: 0603; element_no: C0006
CM7 ICEC7 = CAP-C_5: Package: 0603
ICEC8 = CAP-C_10: Package: 0603
ICEC9 = CAP-C_7: Package: 0603; element_no: C0006
C_VLCD CM4 ICEC10 = CAP-C: Package: 0603
CM6 ICEC11 = CAP-C_6: Package: 0603
ICEC12 = CAP-C_8: Package: 0603; element_no: C0004
CT2 CT4-CT7 CT13 ICECT1-ICECT3 = C_10uF_10V
D3 ICED1 = D_SS24A
ICED3 = CAP-C_9: Package: 0603; element_no: C0004
D2 ICED4 = D_SS24A_1
ICEJ1 = HEADER_5
ICEJ2 = HEADER_4_v2
HJ2 ICEJ3 J2 = micro_USB_5pin_0
ICEJ4 JP1 = HEADER_5X2
ICEJPR1 = HEADER_3_0
ICEJPR2 JPR_VBAT = HEADER_3
ICEL1 L4 L11 = FERRITE_BEAD
ICEL2 L16 = FERRITE_BEAD_1
ICER1 R72 = R_0_6: Package: 0603
ICER2 = R_0_8: Package: 0603
ICER3 R9 R64 = R_0_3: Package: 0603
ICER4 R4 R18 = R_0_2: Package: 0603
ICER5 R2 R8 R19 = R_0_1: Package: 0603
ICER6 = R_33
ICER7 = R_33_1
ICER8 R65 = R_0_5: Package: 0603
ICER9 = R_0_7: Package: 0603
ICER18 R10 R20 R73 RS1 = R_0: Package: 0603
ICER19 R62 = R_0_4: Package: 0603
ICERP1 RP1 RP2 = R-PACK8_0
ICES0 POWER = LED_0_2: Package: KP-2012; Vendor: Kingbright
ICES1 LEDY = LED_0_1: Package: KP-2012; Vendor: Kingbright
ICES2 = LED_0_3: Package: KP-2012; Vendor: Kingbright
ICES3 LEDG SD_POWER = LED_0: Package: KP-2012; Vendor: Kingbright
ICESW1 = SW_PUSHBUTTON_0
ICESW2 = SW_DIP-4_SM
ICEU1 = M487SIDAE_0: M487SIDAE: <M48SSIDAE>
ICEU2 = W25P10_20_40_SOIC_0: Package: SOP8; Vendor: WINBOND
ICEU3 ICEU4 = SN74LV2T45
ICEUP1 UP1-UP3 = TO-247_Regulator_10
ICEUP2 = TO-247_Regulator_0
ICEX1 = Crystal_SMD_1
C1-C4 = CAP_NP
C5 = CAP-C_7: Package: 0805
CB12 CM1 = CAP-C_2: Package: 0603
C_DH12(NC) CM2 = CAP-C_1: Package: 0603
CM3 = CAP-C_4: Package: 0603
CM5 = CAP-C_8: Package: 0603
CB15 CM8 = CAP-C_3: Package: 0603
CT12 = CAP: Package: TANT-R
ETM1 = ETM_Interface_0
L13 L14 = INDUCTOR
R1 = R
SW1 = SW_PUSHBUTTON_1: Package: DIP PUSH BOTTOM
SW2 = SW_PUSHBUTTON: Package: DIP PUSH BOTTOM
T1-T4 = T_POINT
U1 = TC8226LQFP144_23: TC8226LQFP144: M2354_LQFP128
Y2 = Crystal_SMD_2
Y3 = MA306_SM_1
C10 CB14 = CAP-B: Package: 0603
C26 = CAP-B_1: Package: 0603
CT1 = CAP-T: Package: TANT-R
J3 = CON5
U4 = NCT3520U
AMMETER = HEADER_2_3
C11 = C_0.1u: element_no: C0004
C12 = C_0.1u_3: element_no: C0004
C13 = C_0.1u_1: element_no: C0003
C14 = C_0.1u_2: element_no: C0004
C15 = CAP-C: Package: 0603; element_no: C0006
C17 = C_0.1u_5: element_no: C0004
C18 = CAP-C_1: Package: 0603; element_no: C0006
C19 = C_0.1u_4: element_no: C0004
JP4 = HEADER_2_6
JP10 = HEADER_2_7
JP11 = HEADER_2_2
JP12_GND = HEADER_4
JP13_VCC = HEADER_4_1
JP14 = HEADER_2_4
JP15 = HEADER_2_5
L3 = FERRITE_BEAD_3
L15 = FERRITE_BEAD_2
R15 = R_0_2
R16 = R_0_3
SW4_PowerSelect = SW_DIP-4_2
U10 = A8181_SO_4
VDDIO = HEADER_2
VREF1 = HEADER_2_1
JP6-JP9 = HEADER_16X2
NU1 = POWER_CONNECT_0
NU2 = ADC_CONNECT_0
NU3 = PWM1_CONNECT_1
NU4 = PWM0_CONNECT_0
NU5 = SPI_CONNECT_0
CB13 = CAP-B_1
U9 = B8502A-13SB-HPA_(T-Flash_Card)
C6 = C_0.1u
J5 = ADC_CONNECT_3
R3 = R_100
R5 = R_100_1
R6 = R_100_3
R7 = R_100_2
U2 = ESP-12
JLCD_1 = HEADER_24X2

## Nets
1.6V: CB15.1 JPR_VBAT.1 R8.1 U10.5(OUT)
1.8V: ICECT3.1 ICEJPR1.3 ICEJPR2.3 ICER8.1 ICEUP2.2(OUT) ICEUP2.4(OUT)
3.3V: ICEC1.1 ICEC12.1 ICECT1.1 ICEJPR1.1 ICEJPR2.1 ICER18.2 ICER19.2 ICEU1.42(HSUSB_VDD33) ICEU2.8(VCC) ICEU3.1(VCCA) ICEU4.1(VCCA) ICEUP1.2(OUT) ICEUP1.4(OUT)
AVDD: C12.1 C13.1 CT6.1 JP9.24 L3.2 L11.1 U1.120(AVDD) VREF1.1
AVSS: C12.2 C13.2 C14.2 C15.1 CT6.2 JP9.26 L15.2 NU3.7(VSS) U1.122(AVSS)
GND: C1.2 C2.2 C3.2 C4.2 C5.1 C6.2 C10.2 C11.2 C16.1 C17.2 C18.1 C19.2 C26.2 C_VLCD.1 CB12.2 CB13.2 CB14.2 CB15.2 CM1.1 CM2.1 CM3.1 CM4.1 CM5.1 CM6.1 CM7.1 CM8.1 CT1.2 CT2.2 CT4.2 CT5.2 CT7.2 CT12.2 CT13.2 ETM1.3(GND) ETM1.5(GND) ETM1.9(GNDDetect) ETM1.15(GND) ETM1.17(GND) ETM1.19(GND) HJ2.5(GND) ICEC1.2 ICEC2.2 ICEC3.2 ICEC4.2 ICEC5.2 ICEC6.2 ICEC7.1 ICEC8.1 ICEC9.1 ICEC10.1 ICEC11.1 ICEC12.2 ICECT1.2 ICECT2.2 ICECT3.2 ICED3.1 ICEJ1.5 ICEJ2.4 ICEJ3.5(GND) ICEJ4.9 ICEL2.1 ICER1.2 ICER9.1 ICESW1.1 ICESW2.4(A4) ICEU1.6(PB.1) ICEU1.7(PB.0) ICEU1.22(VSS) ICEU1.45(HSUSB_VSS) ICEU1.49(VSS) ICEU1.59(AVSS) ICEU2.4(GND) ICEU3.4(GND) ICEU3.5(DIR) ICEU4.4(GND) ICEU4.5(DIR) ICEUP1.1(GND) ICEX1.2(GND) ICEX1.4(GND) J2.5(GND) J3.5 J5.2(GND) JP1.10 JP4.1 JP4.2 JP6.11 JP7.11 JP8.7 JP8.20 JP9.7 JP9.16 JP10.1 JP10.2 JP11.1 JP11.2 JP12_GND.1 JP12_GND.2 JP12_GND.3 JP12_GND.4 L4.1 L15.1 NU1.6(VSS) NU1.7(VSS) NU5.6(GND) POWER.2 R7.2 R10.2 R19.2 SD_POWER.2 SW1.1 SW2.1 T1.1 T2.1 T3.1 T4.1 U1.11(VSS) U1.39(VSS) U1.52(VSS) U1.75(VSS) U1.103(VSS) U1.112(VSS) U2.15(GND) U4.2(GND) U9.6(VSS) U9.10(GND) U9.11(GND) U9.12(GND) U9.13(GND) U10.2(GND) UP1.1(GND) UP2.1(GND) UP3.1(GND) Y2.2(GND) Y2.4(GND)
VBAT: C18.2 C19.1 JP6.30 JPR_VBAT.2 U1.30(VBAT)
VDD_MCU: AMMETER.2 C11.1 CB12.1 CM3.2 CM4.2 CM5.2 CM6.2 CM7.2 CM8.2 CT2.1 CT12.1 JP6.12 JP7.12 JP8.8 JP8.21 JP9.8 JP9.18 JPR_VBAT.3 L3.1 R16.2 U1.12(VDD) U1.40(VDD) U1.53(VDD) U1.76(VDD) U1.104(VDD) U1.114(VDD) U10.1(IN) U10.3(SHDN#)
VDDIO: C16.2 C17.1 JP8.29 R15.2 U1.61(VDDIO) VDDIO.2
VDDIO_1.8V: CT13.1 R15.1 UP3.2(OUT) UP3.4(OUT) VDDIO.1
BUSY: ICEJ4.2 ICEU1.27(PA.3) ICEU1.56(PB.12)
D+: HJ2.3(D+) J2.3(D+) J3.3 R20.2
D-: HJ2.2(D-) J2.2(D-) J3.2 R9.2
DM: ICEJ2.2 ICEJ3.2(D-) ICER6.2
DP: ICEJ2.3 ICEJ3.3(D+) ICER7.2
ETMCK_MOSI: ICESW2.8(B1) ICEU1.30(PA.0) ICEU1.52(PC.14)
ETMD0_MISO: ICESW2.7(B2) ICEU1.29(PA.1) ICEU1.53(PB.15)
ETMD2_CK: ICEJ4.4 ICEU1.28(PA.2) ICEU1.55(PB.13)
GREEN: ICES3.2 ICEU1.63(PB.8)
HXT_I: ICEC11.2 ICEU1.16(PF.3) ICEX1.1(XIN)
HXT_O: ICEC10.2 ICEU1.17(PF.2) ICEX1.3(XOUT)
ICE5V: ICED1.2 ICEJPR1.4 ICEUP1.3(IN) ICEUP2.3(IN) L16.1
ICE_CLK: ICEJ1.3 ICER4.1 ICEU1.34(PF.1)
ICE_DAT: ICEJ1.2 ICER2.1 ICEU1.33(PF.0)
ICE_RST: ICEC9.2 ICEJ1.4 ICER3.2 ICEU1.32(nRESET)
ICELED: ICES0.2 ICEU1.15(PF.4)
ICEVCC: ICEJPR2.2 ICEL1.1
ICEVDD: ICEC4.1 ICEC5.1 ICEC7.2 ICEC8.2 ICECT2.1 ICEJ1.1 ICEL1.2 ICER2.2 ICER3.1 ICER4.2 ICER5.2 ICERP1.1(R1) ICERP1.3(R2) ICERP1.5(R3) ICERP1.7(R4) ICEU1.13(VBAT) ICEU1.23(VDD) ICEU1.31(VDDIO) ICEU1.51(VDD) ICEU1.57(AVDD) ICEU1.58(VREF) ICEU3.8(VCCB) ICEU4.8(VCCB)
IO0_ESP12: J5.1(GPIO) JP6.18 U1.18(PD.12/CLKO) U2.18(IO0)
ISPLED: ICES1.2 ICEU1.19(PC.6)
KEY1: ICER5.1 ICESW1.2 ICEU1.18(PC.7)
M2354_RXD: ICEJ4.10 ICESW2.2(A2) JP1.9 JP8.19 U1.51(UART0_RXD/PA.6)
M2354_TXD: ICEJ4.8 ICESW2.1(A1) JP1.7 JP8.18 U1.50(UART0_TXD/PA.7)
MCUVCC: ICED4.1 ICEJPR1.2
MCUVCC_DIODE: AMMETER.1 C6.1 CB13.1 ETM1.1(VDD) ICED4.2 ICEJ4.1 JP1.2 JP13_VCC.1 JP13_VCC.2 JP13_VCC.3 JP13_VCC.4 JP14.1 JP14.2 JP15.1 JP15.2 L13.1 NU1.2(VDD) NU5.2(VCC) R2.1 R3.1 R4.1 R5.1 R6.1 R16.1 R18.1 R62.1 R64.1 R65.1 R72.1 R73.1 RP1.2(R1) RP1.4(R2) RP1.6(R3) RP1.8(R4) RP2.2(R1) RP2.4(R2) RP2.6(R3) RP2.8(R4) SW4_PowerSelect.3(B1) U2.8(VCC)
MSG_EN: ICESW2.5(B4) ICEU1.12(PF.6)
NU1_3VCC: CT4.1 NU1.4(3VCC) SW4_PowerSelect.2(A2) UP1.2(OUT) UP1.4(OUT)
NU1_5VCC: C26.1 CT7.1 D2.2 D3.2 L16.2 NU1.5(5VCC) U4.5(IN) UP1.3(IN) UP3.3(IN)
NU1_VIN: CT5.1 NU1.8(VIN) UP2.3(IN)
P1: JP6.1 RP2.3(R2) U1.1(PB.5) U9.2(DAT3)
P2: JP6.2 RP2.5(R3) U1.2(PB.4) U9.1(DAT2)
P3: JP6.3 RP1.5(R3) U1.3(PB.3) U9.8(DAT1)
P4: JP6.4 RP1.7(R4) U1.4(PB.2) U9.7(DAT0)
P5: JP6.5 NU4.7(D6) U1.5(PC.12/UART0_TXD)
P6: JP6.6 NU4.8(D7) U1.6(PC.11/UART0_RXD)
P7: JP6.7 NU3.2(D9) U1.7(PC.10)
P8: JP6.8 NU3.1(D8) U1.8(PC.9)
P9: JP6.9 U1.9(PB.1) U9.5(CLK)
P10: JP6.10 RP2.1(R1) U1.10(PB.0) U9.3(CMD)
P13: JP6.13 U1.13(PA.11)
P14: JP6.14 U1.14(PA.10)
P15: JP6.15 NU4.2(D1) U1.15(PA.9)
P16: JP6.16 NU4.1(D0) U1.16(PA.8)
P17: JP6.17 R3.2 U1.17(PC.13/CLKO) U2.1(RST)
P19: JP6.19 U1.19(PD.11)
P20: JP6.20 U1.20(PD.10)
P21: JLCD_1.48 JP6.21 NU3.10(I2C_SCL) U1.21(PG.2)
P22: JLCD_1.47 JP6.22 NU3.9(I2C_SDA) U1.22(PG.3)
P23: JLCD_1.46 JP6.23 U1.23(PG.4)
P24: JP6.24 R62.2 SW2.2 U1.24(PF.11)
P25: JP6.25 U1.25(PF.10)
P26: JP6.26 U1.26(PF.9)
P27: JP6.27 U1.27(PF.8)
P28: JP6.28 U1.28(PF.7)
P29: JP6.29 U1.29(PF.6)
P31: C1.1 JP6.31 U1.31(X32_IN/PF.5) Y3.2
P32: C2.1 JP6.32 U1.32(X32_OUT/PF.4) Y3.1
P33: JLCD_1.45 JP8.1 U1.33(RTC_LDO/PH.4)
P34: JLCD_1.44 JP8.2 U1.34(PH.5)
P35: JLCD_1.43 JP8.3 U1.35(PH.6)
P36: JLCD_1.42 JP8.4 U1.36(PH.7)
P37: C3.1 JP8.5 R1.1 U1.37(XT1_IN/PF.3) Y2.1(XIN)
P38: C4.1 JP8.6 R1.2 U1.38(PF.2/XT1_OUT) Y2.3(XOUT)
P41: ETM1.20(TRACEDATA[3]) JLCD_1.41 JP8.9 U1.41(PE.8)
P42: ETM1.18(TRACEDATA[2]) JLCD_1.40 JP8.10 U1.42(PE.9)
P43: ETM1.16(TRACEDATA[1]) JLCD_1.39 JP8.11 U1.43(PE.10)
P44: ETM1.14(TRACEDATA[0]) JP8.12 U1.44(PE.11)
P45: ETM1.12(TRACECLK) JP8.13 U1.45(PE.12)
P46: JP8.14 U1.46(PE.13) U2.7(IO13)
P47: JP8.15 R7.1 U1.47(PC.8) U2.16(IO15)
P48: JP8.16 U1.48(PC.7) U2.21(RXD)
P49: JP8.17 U1.49(PC.6) U2.22(TXD)
P54: CM2.2 JP8.22 U1.54(LDO_CAP)
P55: JLCD_1.38 JP8.23 U1.55(PA.5)
P56: JLCD_1.37 JP8.24 U1.56(PA.4)
P57: JLCD_1.36 JP8.25 NU3.3(D10) U1.57(PA.3)
P58: JLCD_1.35 JP8.26 NU3.6(D13) U1.58(PA.2)
P59: JLCD_1.34 JP8.27 NU3.5(D12) U1.59(UART0_TXD/PA.1)
P60: JLCD_1.33 JP8.28 NU3.4(D11) U1.60(UART0_RXD/PA.0)
P62: JLCD_1.32 JP8.30 U1.62(PE.14)
P63: JLCD_1.31 JP8.31 U1.63(PE.15)
P64: C5.2 ETM1.10(nRESET) ICEJ4.7 ICEU1.14(PF.5) JP1.8 JP8.32 NU1.3(MCU_RESET) NU5.5(RESET) R2.2 SW1.2 U1.64(nRESET)
P65: ETM1.2(SDWIO) ICEJ4.3 ICEU1.10(PA.9) JP1.4 JP7.1 R72.2 U1.65(PF.0/ICE_DAT)
P66: ETM1.4(SWDCLK) ICEJ4.5 ICEU1.9(PA.10) JP1.6 JP7.2 R73.2 U1.66(PF.1/ICE_CLK)
P67: JLCD_1.24 JP7.3 U1.67(PD.9)
P68: JLCD_1.23 JP7.4 U1.68(PD.8)
P69: JLCD_1.22 JP7.5 U1.69(PC.5)
P70: JLCD_1.21 JP7.6 U1.70(PC.4)
P71: JLCD_1.20 JP7.7 U1.71(PC.3)
P72: JLCD_1.19 JP7.8 U1.72(PC.2)
P73: JLCD_1.18 JP7.9 NU4.3(D2) U1.73(PC.1)
P74: JLCD_1.17 JP7.10 NU4.4(D3) U1.74(PC.0)
P77: JLCD_1.30 JP7.13 U1.77(PG.9)
P78: JLCD_1.29 JP7.14 U1.78(PG.10)
P79: JLCD_1.28 JP7.15 U1.79(PG.11)
P80: JLCD_1.27 JP7.16 U1.80(PG.12)
P81: JLCD_1.26 JP7.17 U1.81(PG.13)
P82: JLCD_1.25 JP7.18 U1.82(PG.14)
P83: JLCD_1.16 JP7.19 U1.83(PG.15/CLKO)
P84: JLCD_1.15 JP7.20 U1.84(PD.7)
P85: JLCD_1.14 JP7.21 U1.85(PD.6)
P86: JP7.22 U1.86(PD.5)
P87: JP7.23 U1.87(PD.4)
P88: JP7.24 LEDY.2 U1.88(UART0_TXD/PD.3)
P89: JP7.25 LEDG.2 U1.89(UART0_RXD/PD.2)
P90: C_DH12(NC).1 JP7.26 U1.90(PD.1)
P91: C_DH12(NC).2 JP7.27 U1.91(PD.0)
P92: C_VLCD.2 JP7.28 U1.92(PD.13)
P94: JP7.30 R9.1 U1.94(USB_D-/PA.13)
P95: JP7.31 R20.1 U1.95(UART0_TXD/UDB_D+/PA.14)
P96: HJ2.4(ID) J2.4(ID) J3.4 JP7.32 U1.96(UART0_RXD/USB_OTG_ID/PA.15)
P97: JLCD_1.13 JP9.1 NU4.5(D4) U1.97(PE.7)
P98: JLCD_1.12 JP9.2 NU4.6(D5) U1.98(PE.6)
P99: JLCD_1.11 JP9.3 U1.99(PE.5)
P100: JLCD_1.10 JP9.4 U1.100(PE.4)
P101: JLCD_1.9 JP9.5 U1.101(PE.3)
P102: JLCD_1.8 JP9.6 U1.102(PE.2)
P105: JLCD_1.7 JP9.9 NU5.1(SPI2_MISO) U1.105(PE.1)
P106: JLCD_1.6 JP9.10 NU5.4(SPI2_MOSI) U1.106(PE.0)
P107: JLCD_1.5 JP9.11 NU5.3(SPI2_CLK) U1.107(PH.8)
P108: JLCD_1.4 JP9.12 NU5.7(SPI2_SS) U1.108(PH.9)
P109: JLCD_1.3 JP9.13 NU5.8(GPIO) U1.109(PH.10/UART0_TXD)
P110: JLCD_1.2 JP9.14 U1.110(PH.11/UART0_RXD)
P111: JLCD_1.1 JP9.15 U1.111(PD.14)
P113: JP9.17 L14.1 U1.113(VSW)
P115: CM1.2 JP9.19 L14.2 U1.115(LDO_CAP)
P116: JP9.20 R19.1 U1.116(PB.15) U4.4(EN/EN#)
P117: JP9.21 R18.2 U1.117(PB.14/CLKO) U4.3(OC#)
P118: JP9.22 U1.118(PB.13/UART0_TXD)
P119: JP9.23 RP1.3(R2) U1.119(PB.12/UART0_RXD) U9.9(CD)
P123: JP9.27 NU2.1(A0) U1.123(PB.11)
P124: JP9.28 NU2.2(A1) U1.124(PB.10)
P125: JP9.29 NU2.3(A2) U1.125(PB.9/UART0_TXD)
P126: JP9.30 NU2.4(A3) U1.126(PB.8/UART0_RXD)
P127: JP9.31 NU2.5(A4) U1.127(PB.7)
P128: JP9.32 NU2.6(A5) U1.128(PB.6)
RED: ICES2.2 ICEU1.62(PB.9)
SPIM_CLK: ICEU1.38(PC.2) ICEU4.7(B1)
SPIM_CLK_LV: ICEU2.6(CLK) ICEU4.2(A1)
SPIM_CS: ICEU1.37(PC.3) ICEU3.7(B1)
SPIM_CS_LV: ICEU2.1(CS#) ICEU3.2(A1)
SPIM_MISO0: ICEU1.39(PC.1) ICEU2.2(DO)
SPIM_MOSI0: ICEU1.40(PC.0) ICEU4.6(B2)
SPIM_MOSI0_LV: ICEU2.5(DI) ICEU4.3(A2)
SWO: ICEJ4.6 ICEU1.26(PA.4)
USB_HS_CAP: ICEC2.1 ICEU1.47(HSUSB_VDD12_CAP)
USB_HS_D+: ICER7.1 ICEU1.46(HSUSB_D+)
USB_HS_D-: ICER6.1 ICEU1.44(HSUSB_D-)
USB_HS_REXT: ICER1.1 ICEU1.41(HSUSB_VRES)
USB_HS_VBUS: ICED1.1 ICED3.2 ICEJ2.1 ICEJ3.1(VBUS) ICEU1.43(HSUSB_VBUS)
USB_VBUS: C10.1 CT1.1 D3.1 HJ2.1(VBUS) J2.1(VBUS) J3.1 JP7.29 U1.93(USB_VBUS/PA.12) U4.1(OUT)
VREF: C14.1 C15.2 JP9.25 L11.2 NU3.8(VREF) U1.121(VREF) VREF1.2
N16840819: ICEC6.1 ICEU1.24(LDO_CAP)
N16840960: ICEC3.1 ICEU1.50(LDO_CAP)
N17019924: ICER8.2 ICER9.2 ICEUP2.1(ADJ)
N17029977: ICERP1.8(R4) ICES3.1
N17029979: ICERP1.6(R3) ICES2.1
N17030004: ICERP1.4(R2) ICES1.1
N17030010: ICERP1.2(R1) ICES0.1
N17042369: ICEJ3.6(Shield) ICEJ3.7(Shield) ICEJ3.8(Shield) ICEJ3.9(Shield) ICEJ3.10(Shield) ICEJ3.11(Shield) ICEL2.2
N17150802: POWER.1 R4.2
N17155328: ICER18.1 ICEU2.7(HOLD#)
N17155343: ICER19.1 ICEU2.3(WP#)
N17251993: CB14.1 L13.2 RS1.1 U9.4(VDD)
N17251997: RS1.2 SD_POWER.1
N17322338: LEDG.1 R64.2
N17323123: LEDY.1 R65.2
N17777399: D2.1 UP2.2(OUT) UP2.4(OUT)
N17806454: HJ2.6(Shield) HJ2.7(Shield) HJ2.8(Shield) HJ2.9(Shield) HJ2.10(Shield) HJ2.11(Shield) J2.6(Shield) J2.7(Shield) J2.8(Shield) J2.9(Shield) J2.10(Shield) J2.11(Shield) L4.2
N17889351: R5.2 U2.17(IO2)
N17889376: R6.2 U2.3(EN)
N17921596: R8.2 R10.1 U10.4(SET)

Not connected (* = marked no-connect by the designer): ETM1 6(NC)* 7(NC)* 8(NC)* 11(NC)* 13(NC)*; ICEJ3 4(ID)*; ICESW2 3(A3)* 6(B3)*; ICEU1 1(PB.6)* 2(PB.5)* 3(PB.4)* 4(PB.3)* 5(PB.2)* 8(PA.11)* 11(PA.8)* 20(PA.7)* 21(PA.6)* 25(PA.5)* 35(PC.5) 36(PC.4) 48(HSUSB_ID)* 54(PB.14)* 60(PB.11)* 61(PB.10)* 64(PB.7)*; ICEU3 3(A2)* 6(B2)*; JP1 1* 3* 5*; NU1 1(NC)*; RP1 1(R1)*; RP2 7(R4)*; SW4_PowerSelect 1(A1)* 4(B2)*; U2 2(ADC)* 4(IO16)* 5(IO14)* 6(IO12)* 9(CS0)* 10(MISO)* 11(IO9)* 12(IO10)* 13(MOSI)* 14(SCLK)* 19(IO4)* 20(IO5)*

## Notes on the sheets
sheet 1
- LCD Off-page
sheet 2
- Off-page Connector
- DEBUG
- RESET
- SPI FLASH
- Nu-Trace,   ID0 = 1, ID1 = 1
  Nu-Link2,   ID0 = 0, ID1 = 1
  Nu-LInk2-Me, ID0 = 0, ID1 = 0
- NULINK ID
- KEY
- Power Switch
- VCOM SWITCH
- 12M Crystal
- USB 2.0 HIGH SPEED DEVICES
- LED
- ICE INTERFACE
sheet 3
- WIFI Off-page
sheet 4
- RESET
- UNO Interface
- Analog In
- P1
  P32
- P65
  P96
- ~
- ~
- Digital In0
- BUTTON
- Digital In1
- P33
  P64
- P97
  P128
- ~
- ~
- Hole
- ETM
- ICE Off Page
- WIFI Off-page
- USB1.1 OTG&HOST
- LDO_CAP
- VDD_MCU
- POWER Off Page
- SD CARD
- CRYSTAL
- ICE
- MCU bypass CAP
- LED
sheet 5
- USB1.1 OTG&HOST
- USB1.1 OTG HOST/DEVICE
- High Active
- OC# is Open-drain Pin
sheet 6
- POWER Off Page
- Power Connector
- Power
  Selector
sheet 7
- P1
  P32
- P65
  P96
- ~
- ~
- MCU CONNECTOR
- P33
  P64
- P97
  P128
- ~
- ~
sheet 8
- UNO Interface
- Analog In
- Digital In0
- Digital In1
- UNO INTERFACE
  CONNECTOR
sheet 9
- SD CARD
- SD Card
